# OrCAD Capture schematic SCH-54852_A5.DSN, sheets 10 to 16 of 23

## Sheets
10 C-12 USB PD: size C
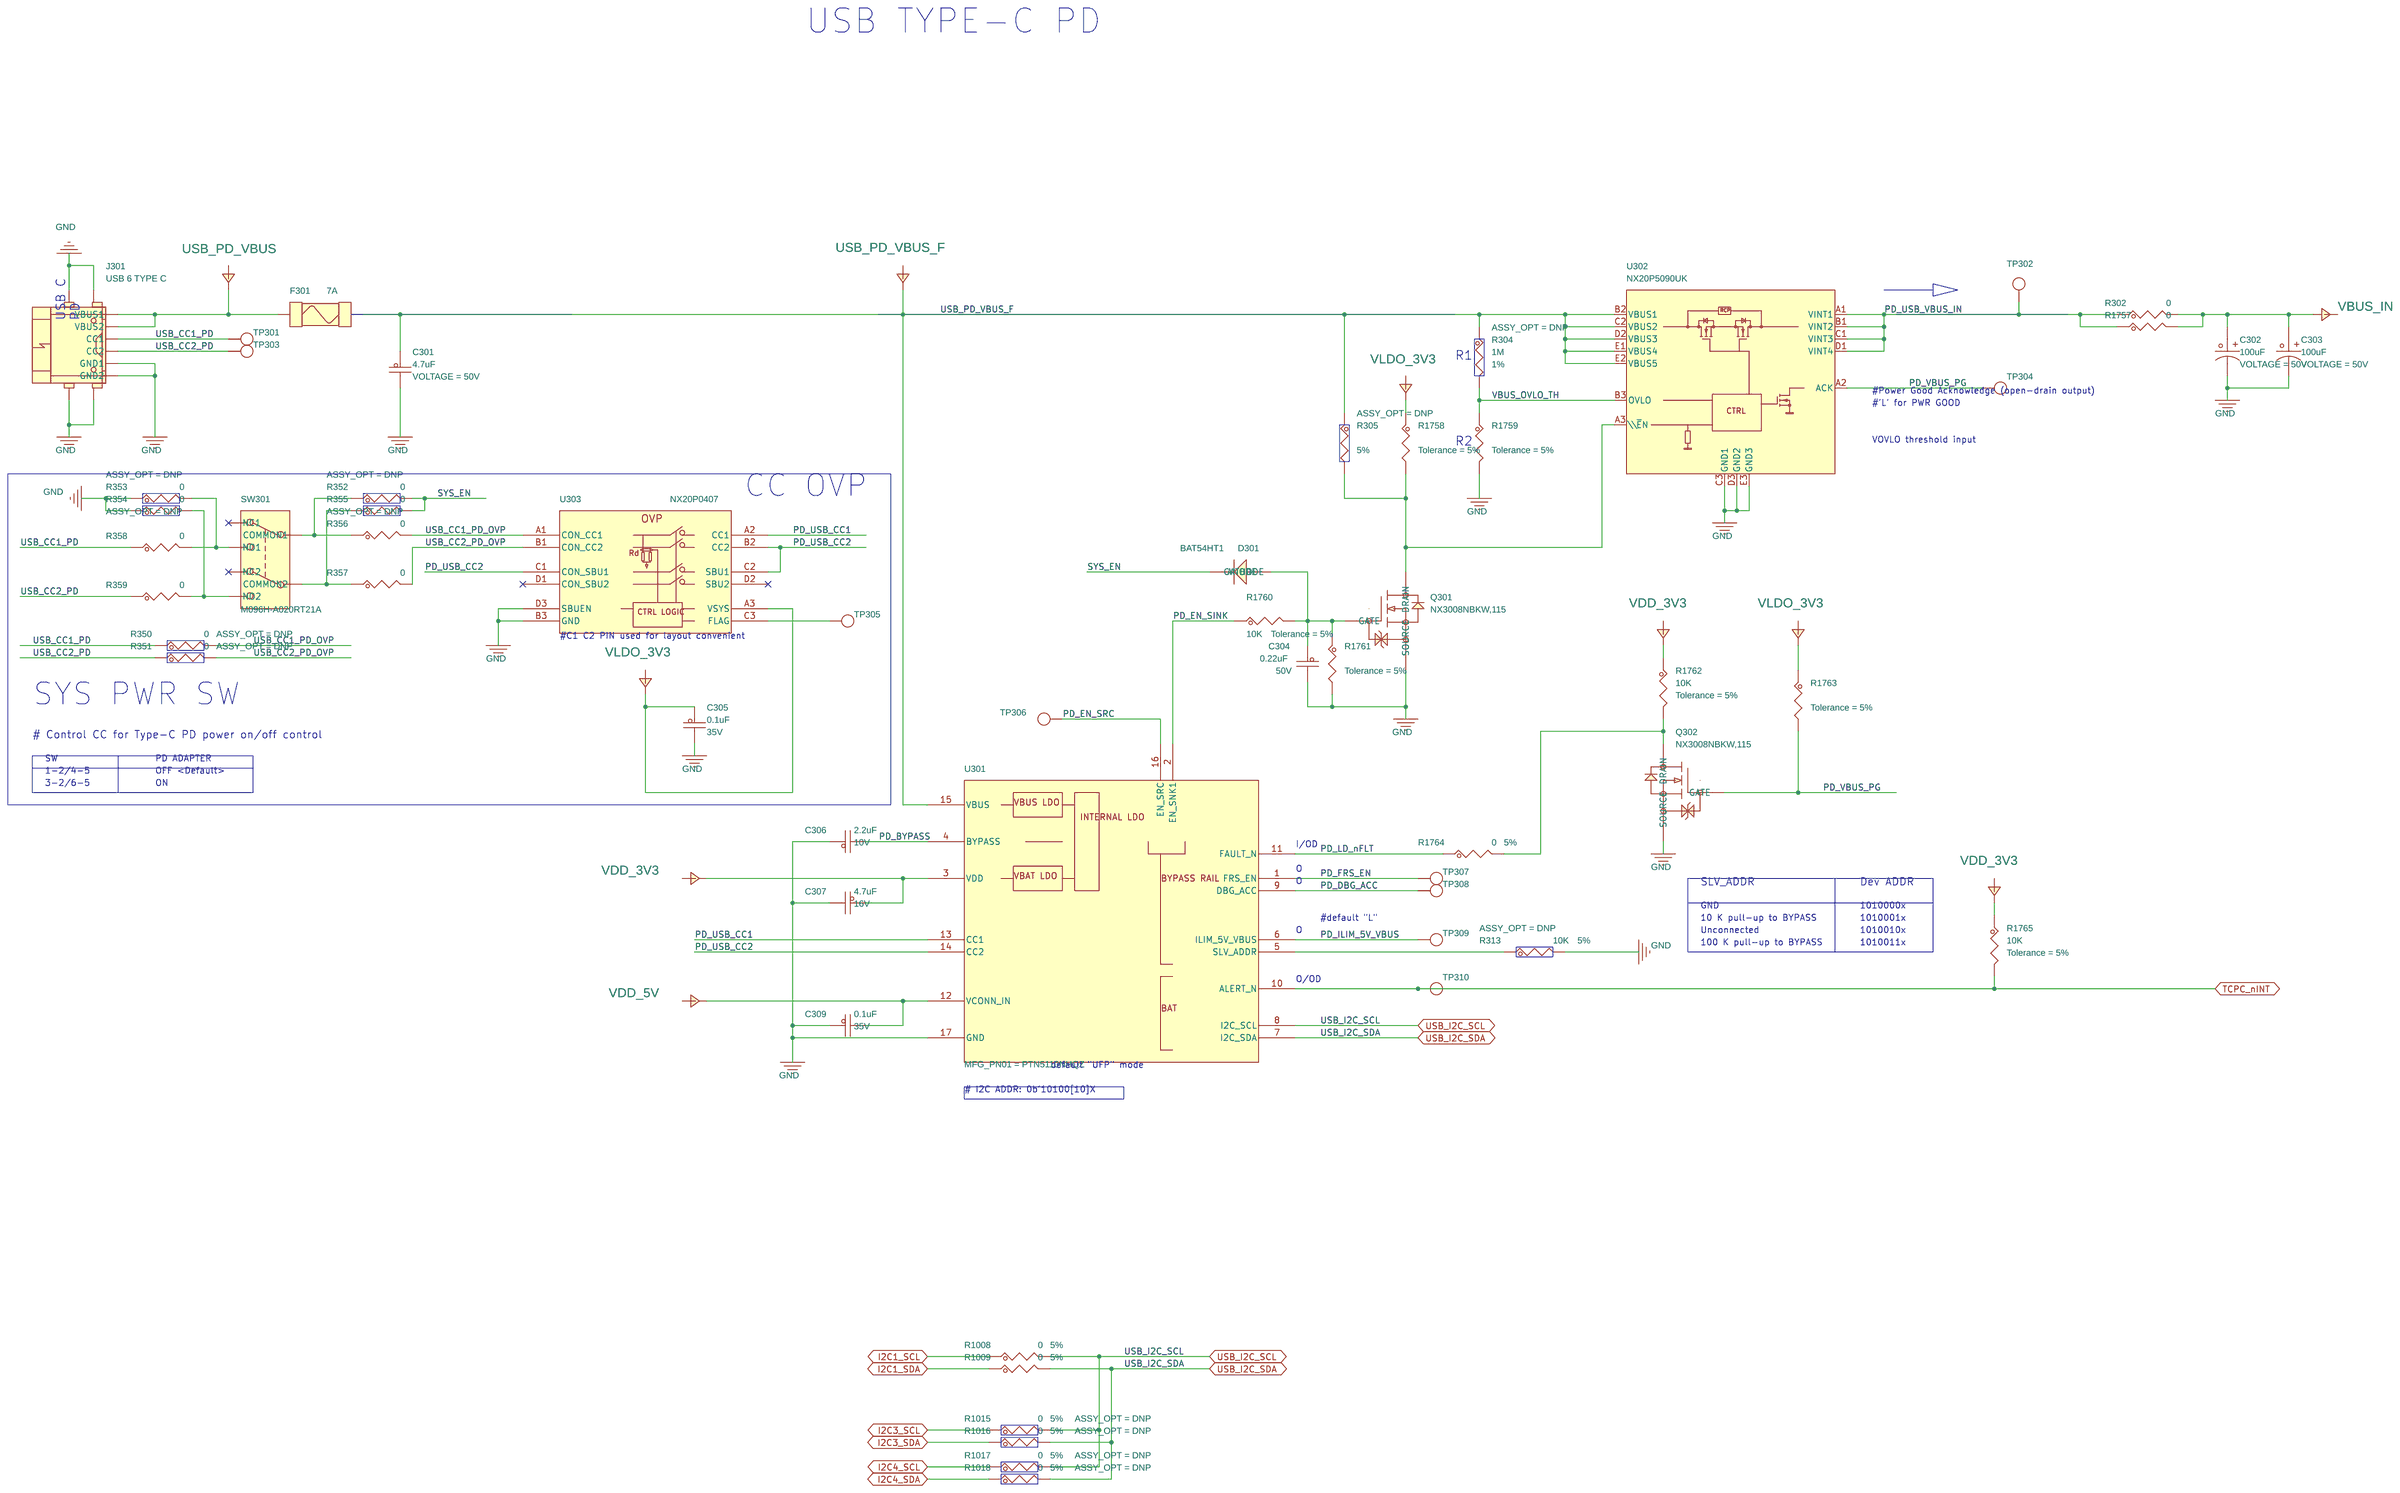
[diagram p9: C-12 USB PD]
11 C-11 SYS PWR: size C
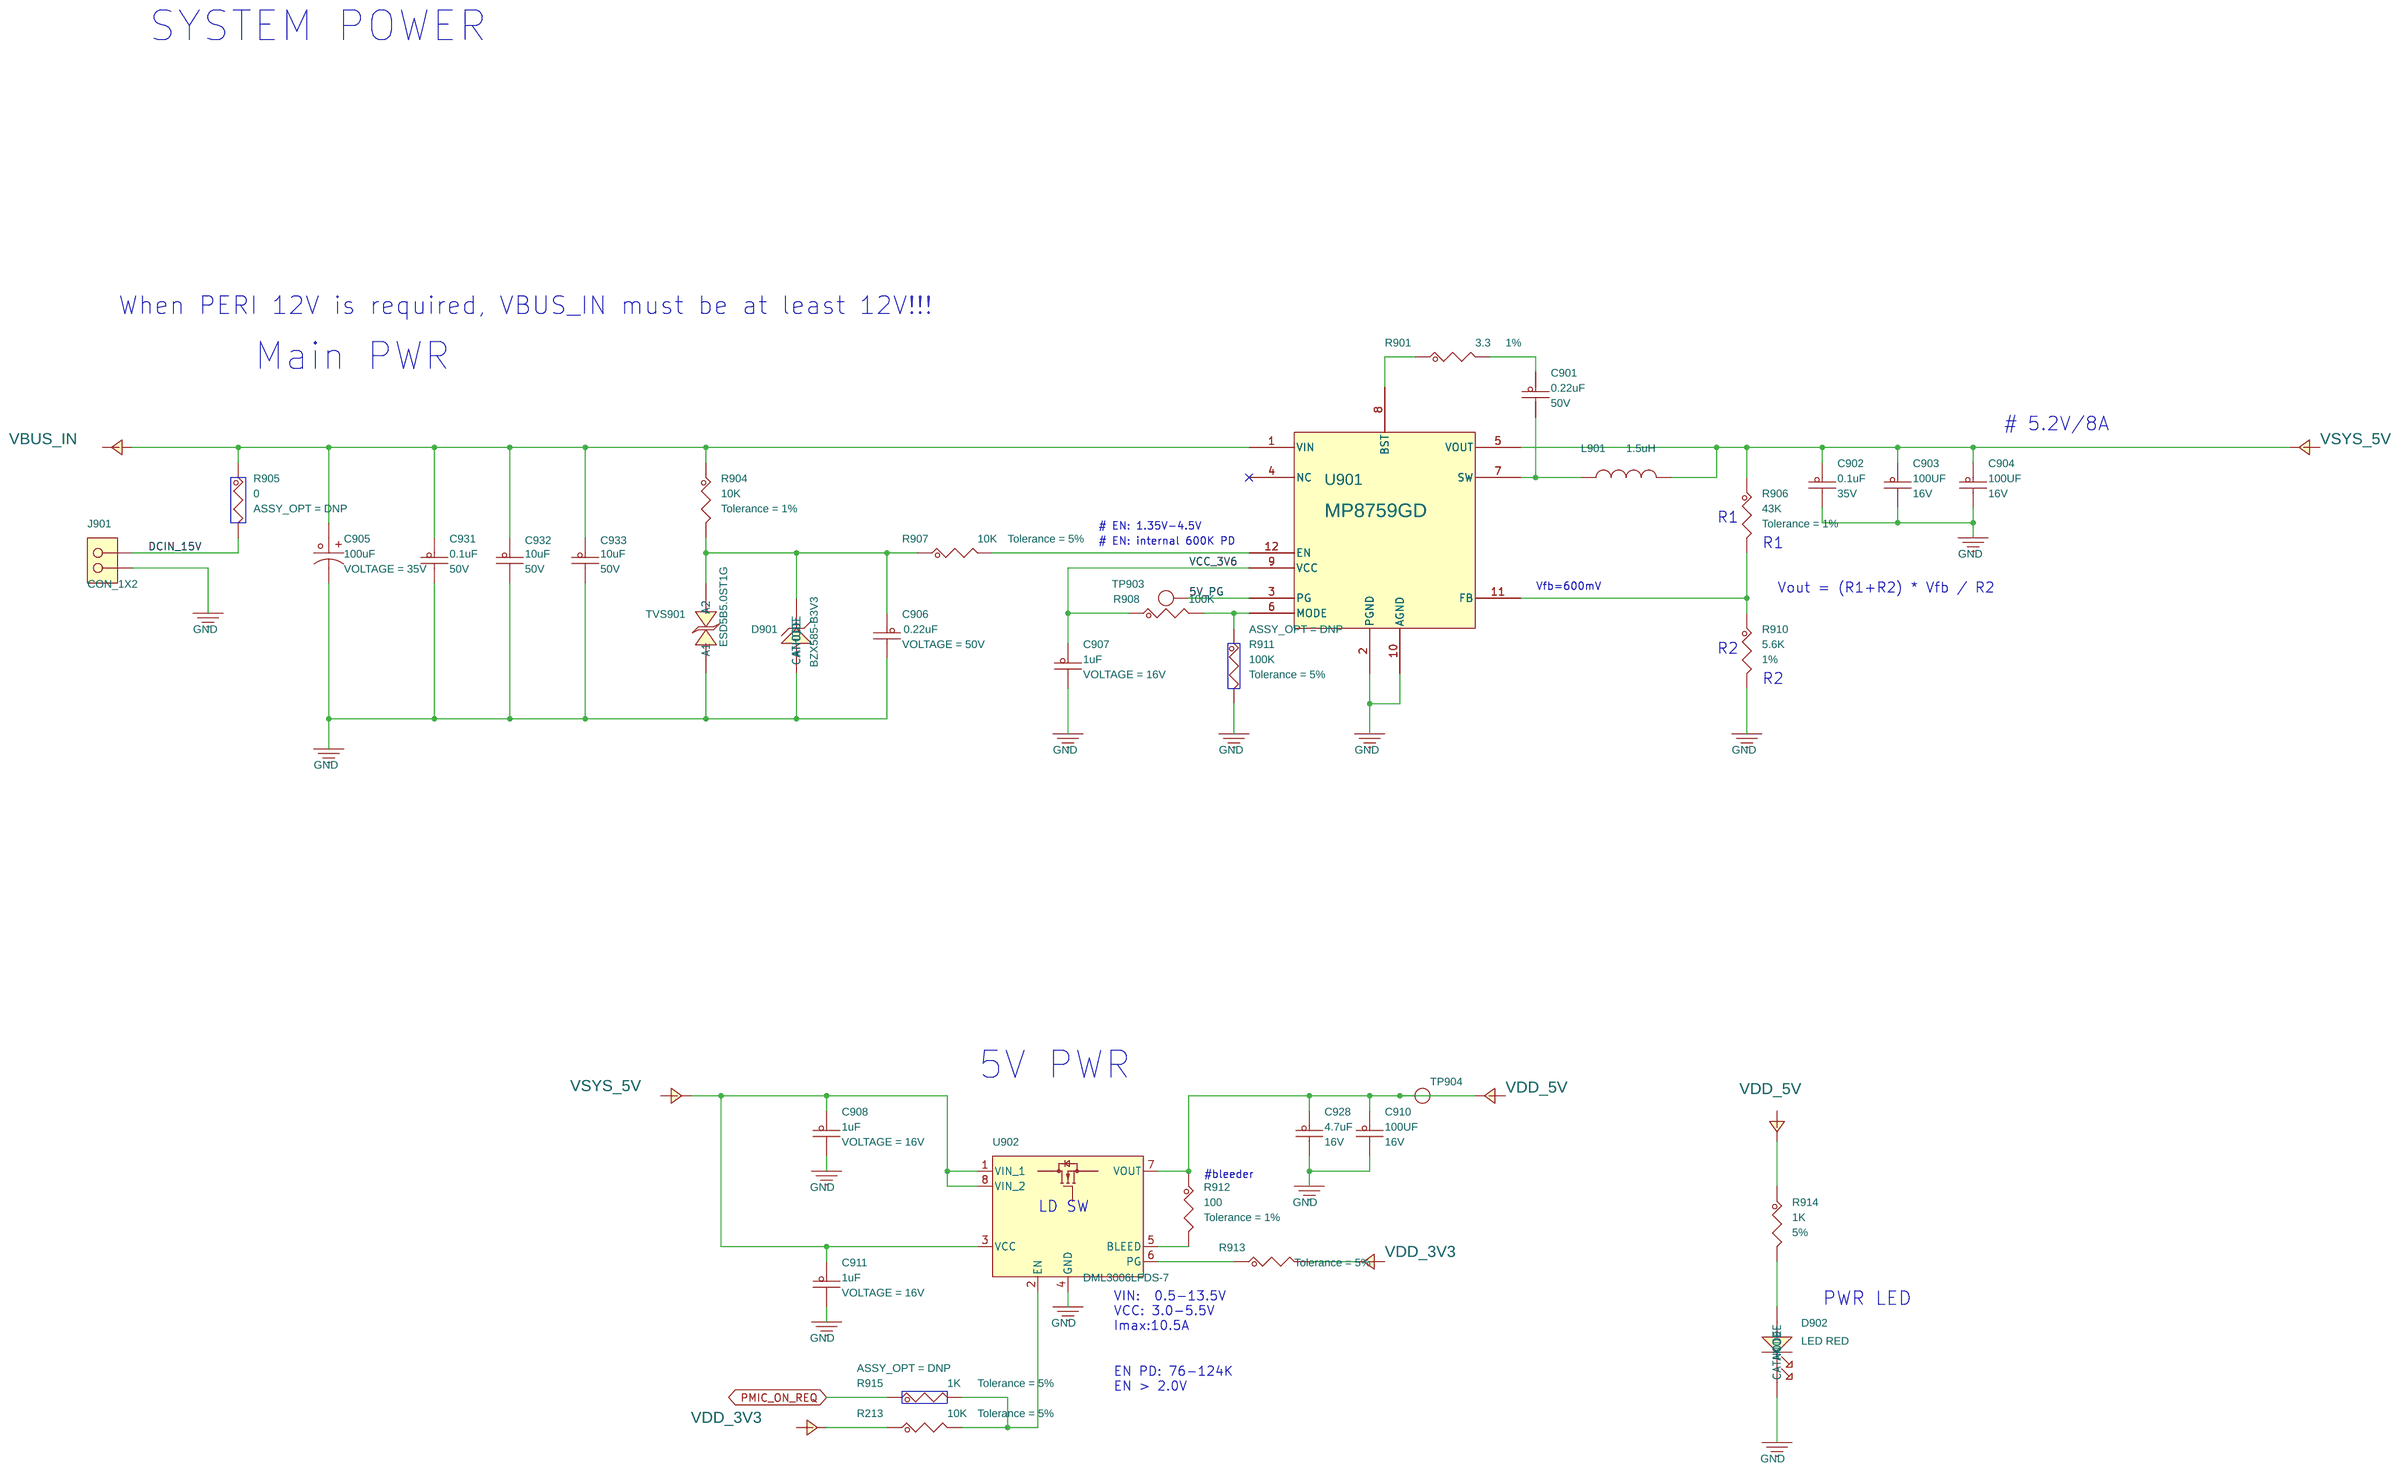
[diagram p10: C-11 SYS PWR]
12 C-10 IO MUX: size C
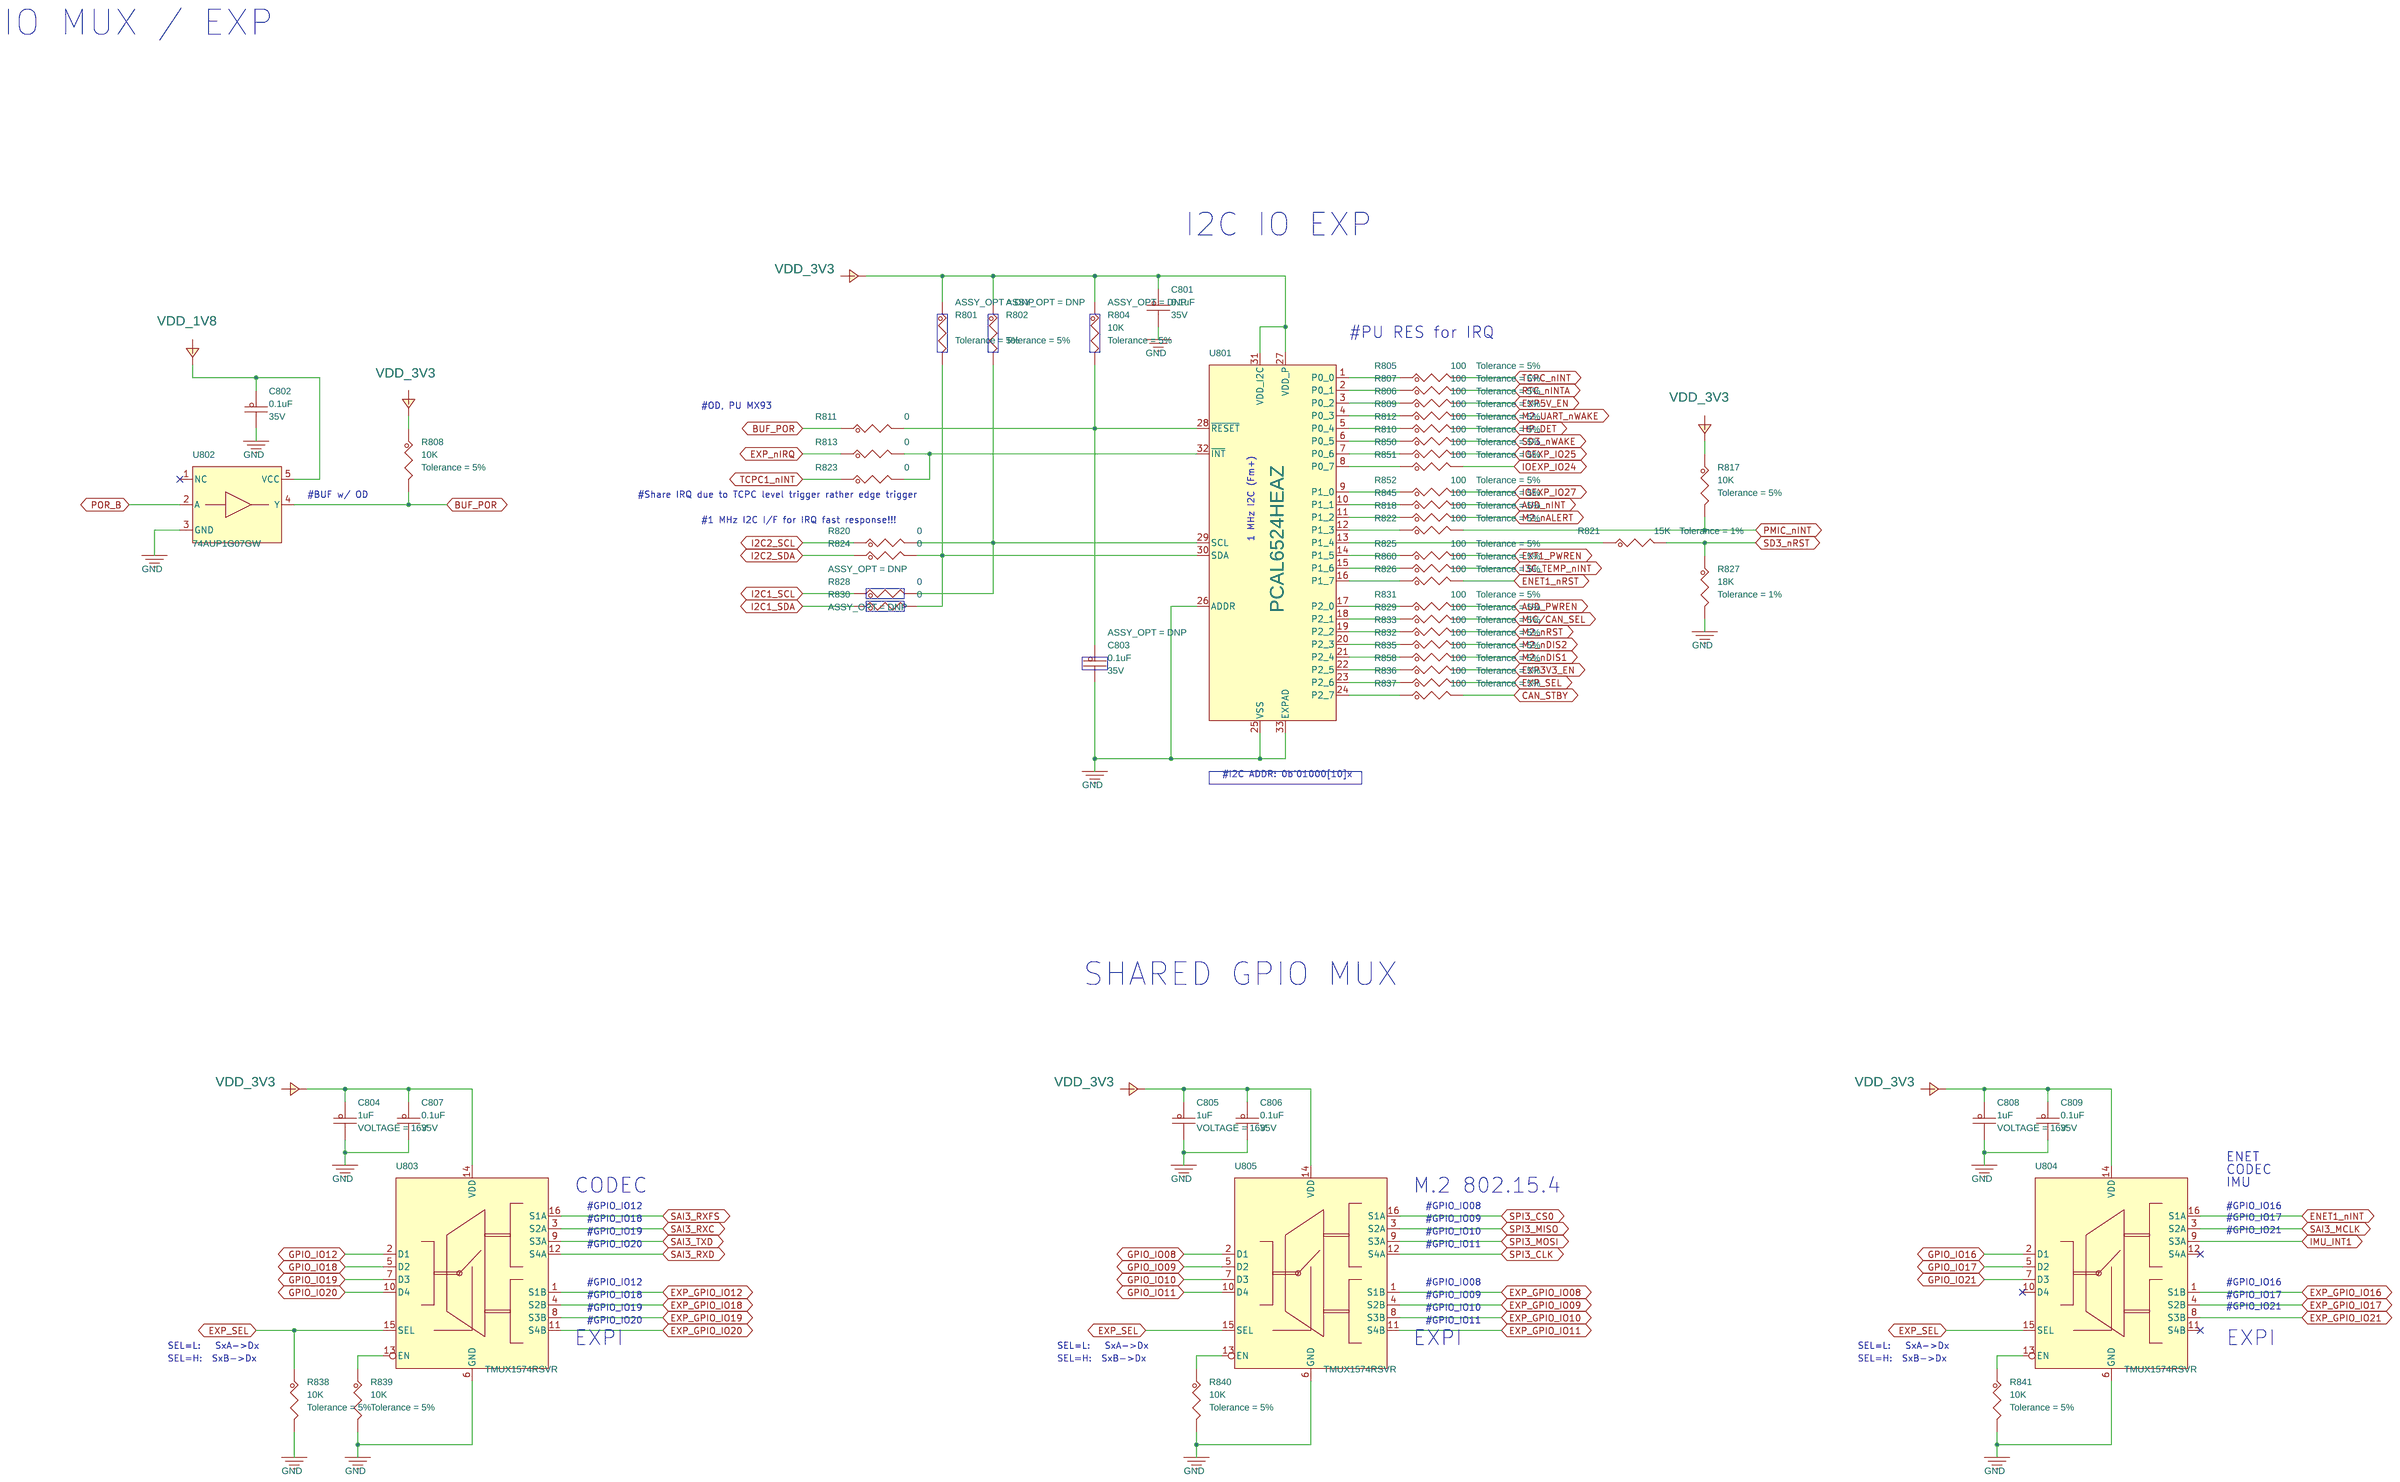
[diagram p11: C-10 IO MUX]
13 A-01 COVER
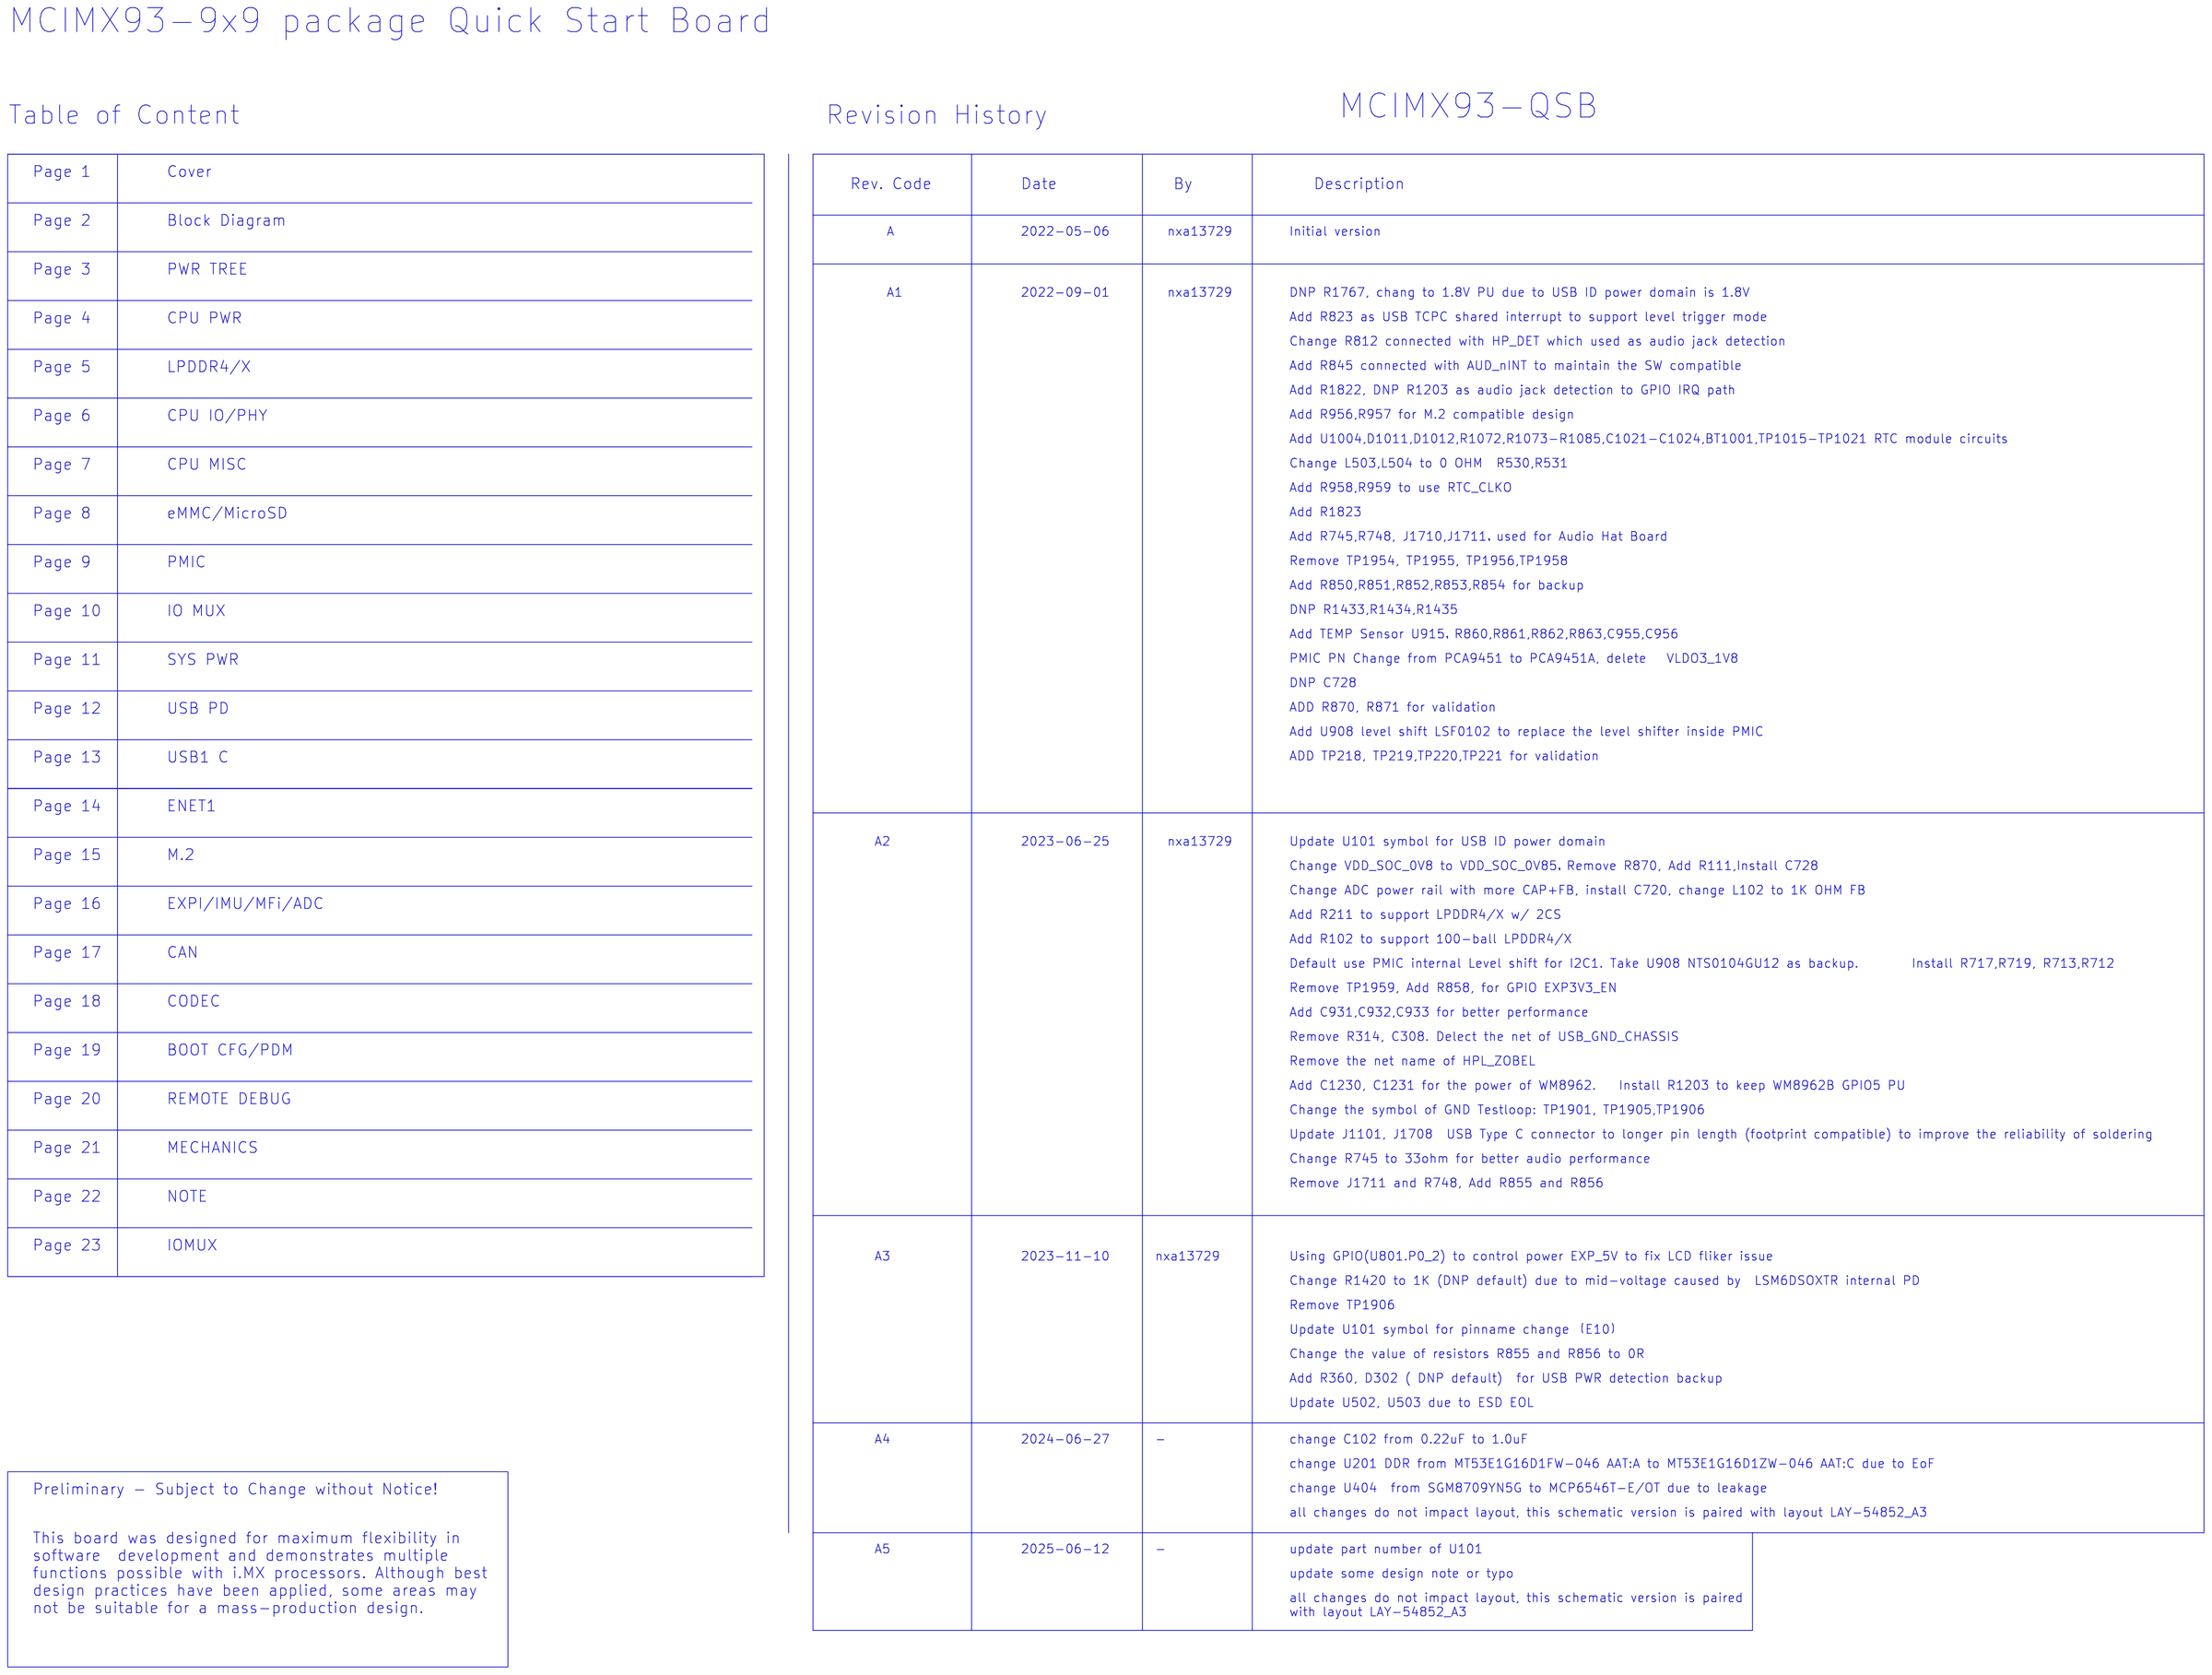
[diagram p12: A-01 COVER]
14 A-02 BLOCK DIAGRAM
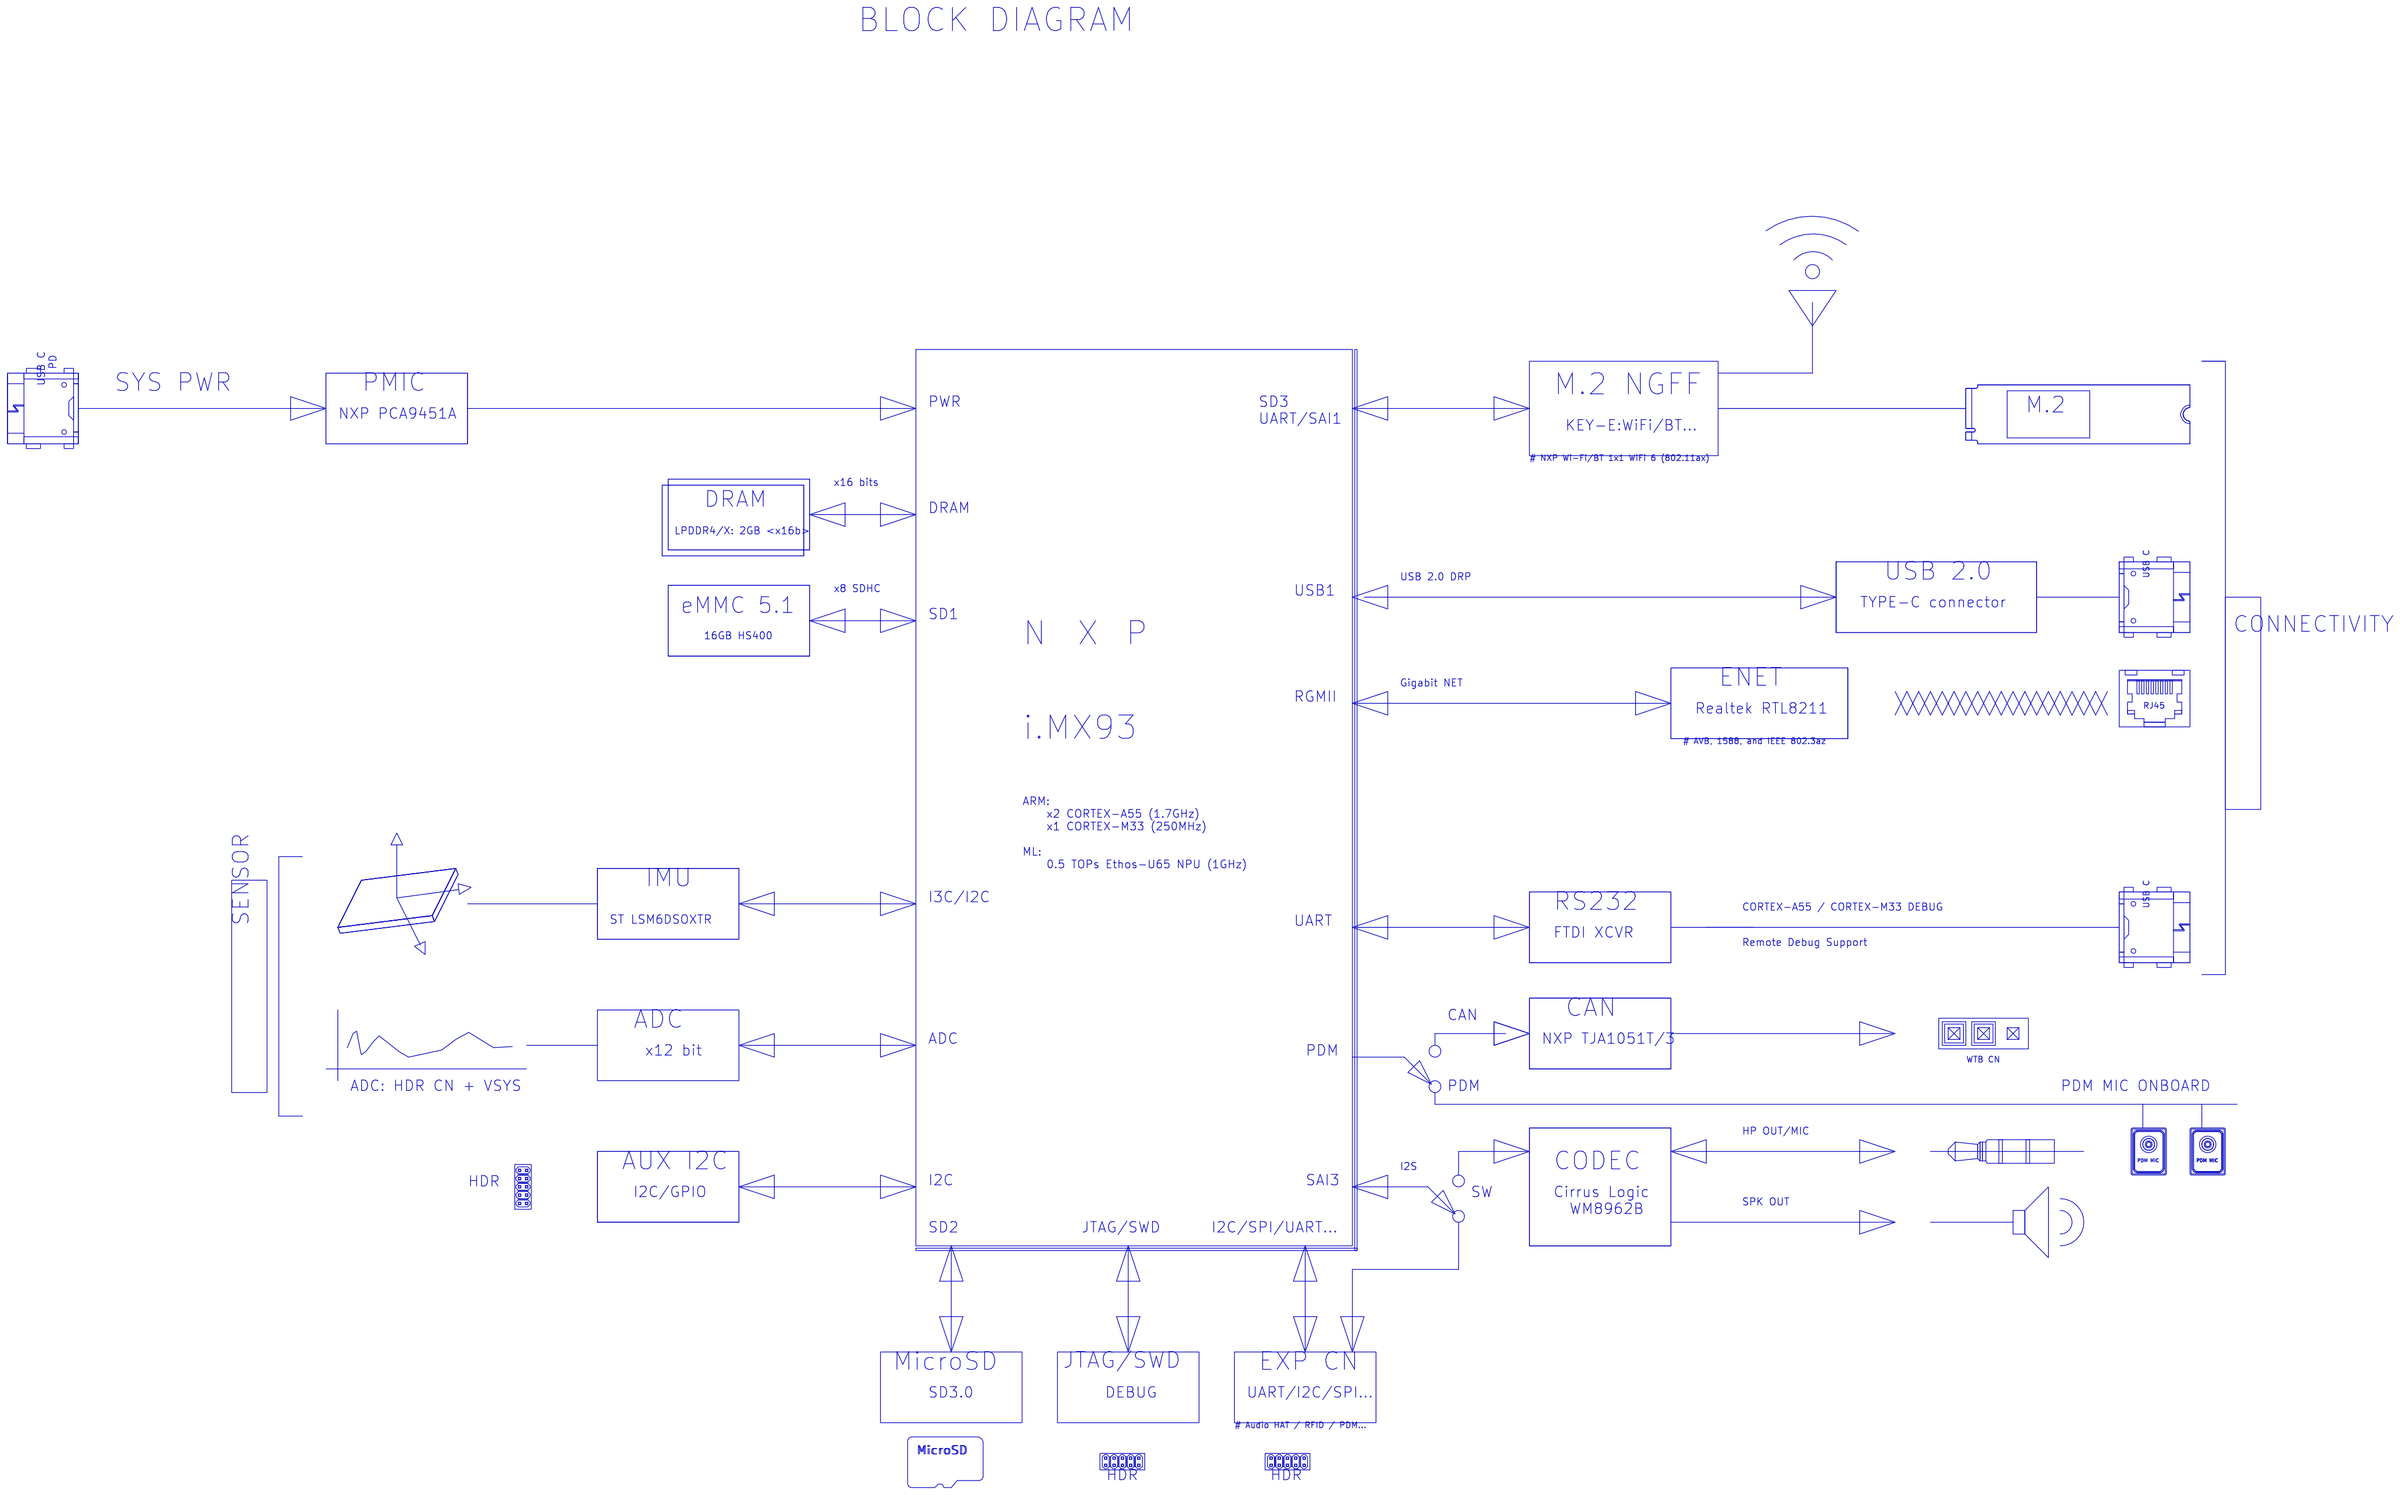
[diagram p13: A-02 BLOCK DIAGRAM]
15 A-03 PWR TREE
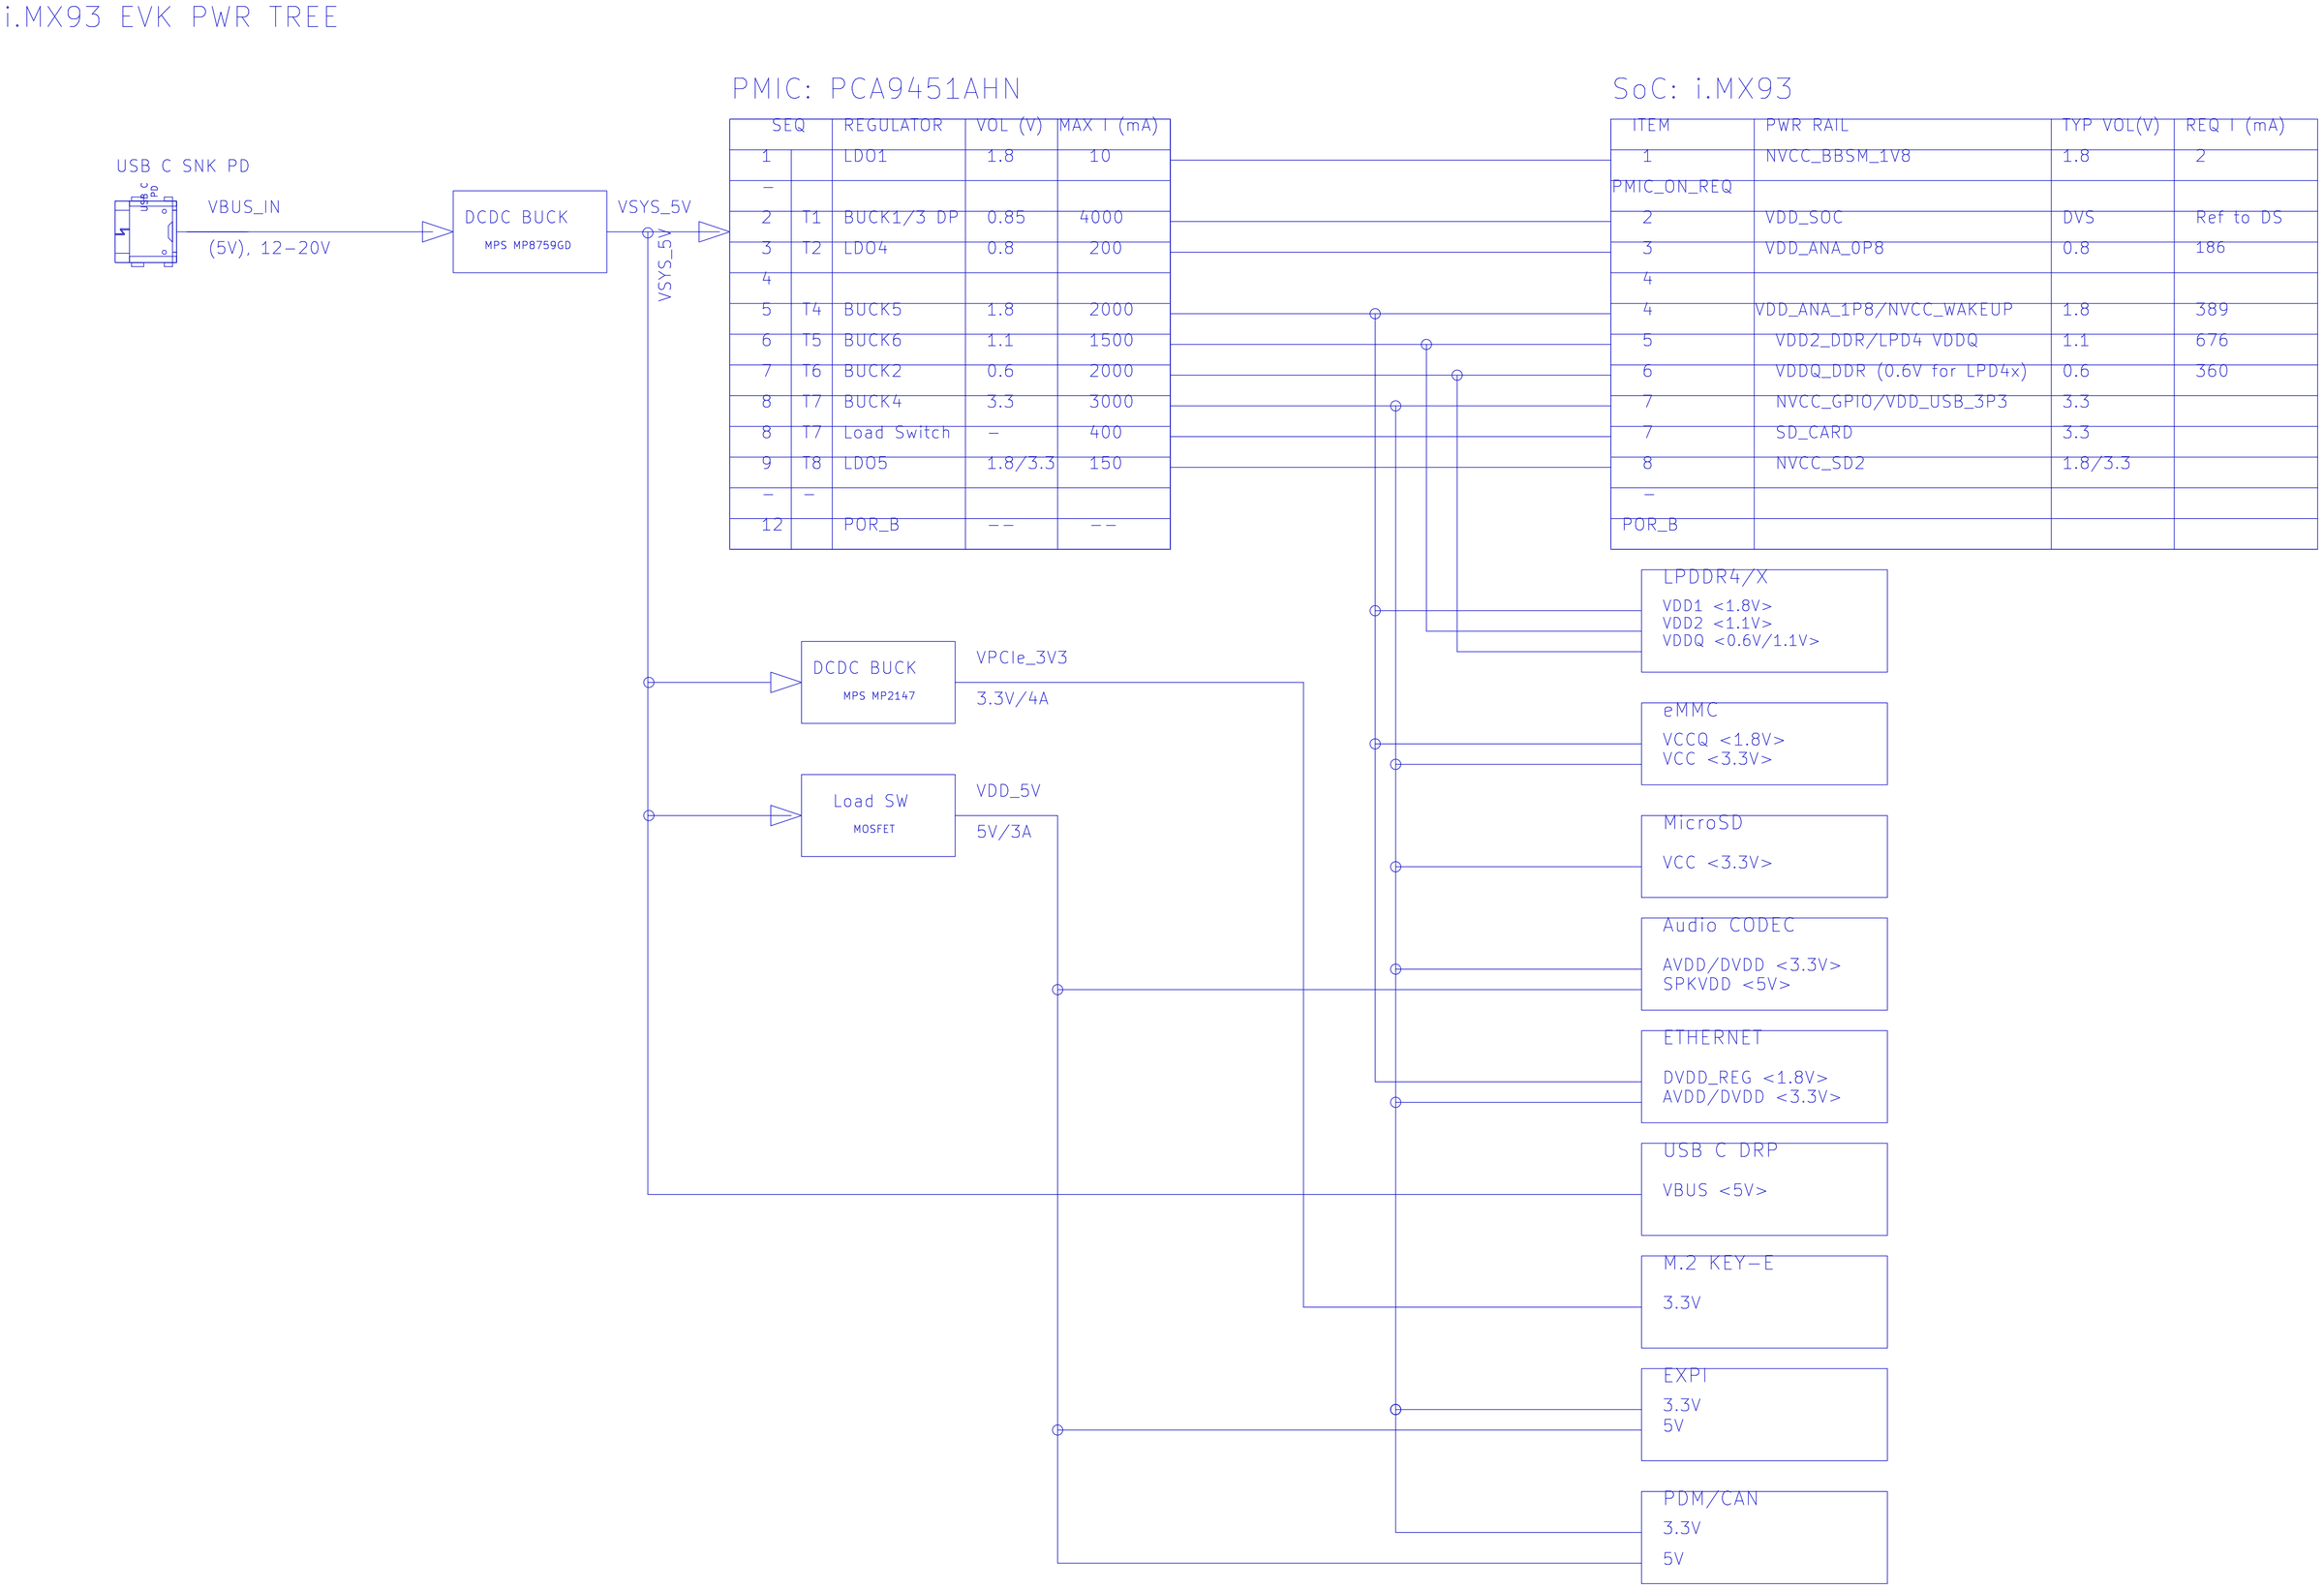
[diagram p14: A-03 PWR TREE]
16 C-04 CPU PWR: size C
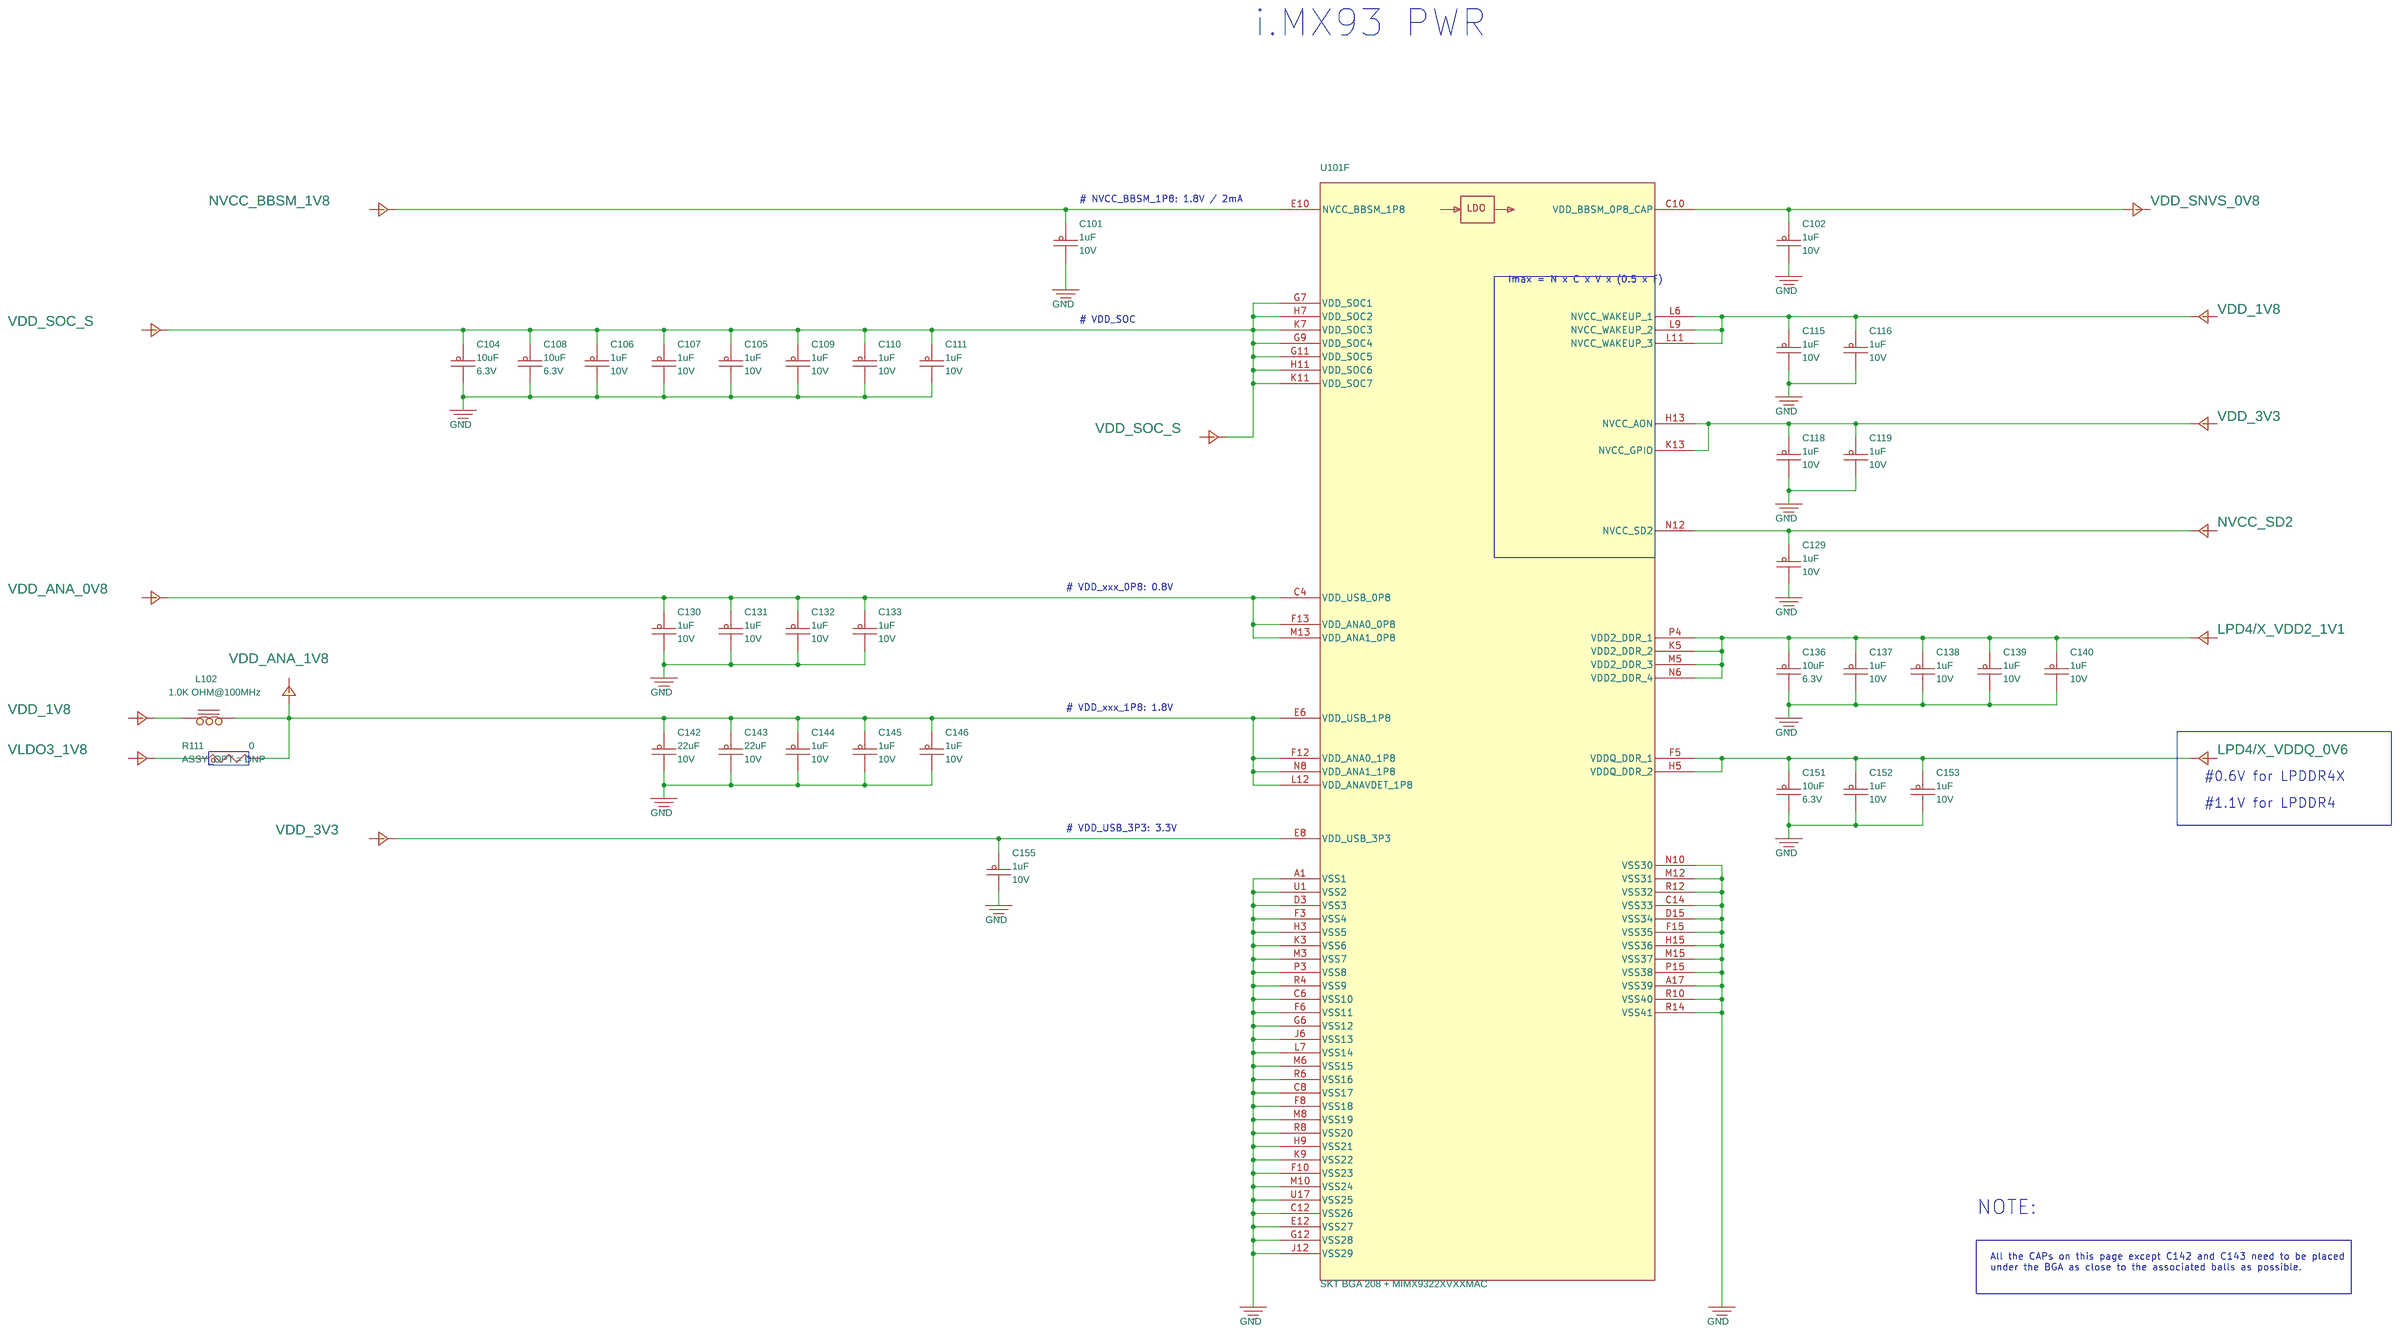
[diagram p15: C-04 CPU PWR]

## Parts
sheet C-04 CPU PWR
C101  1uF  [0201_CC]
C102  1uF  [0201_CC]
C104  10uF  [0402_CC]
C105  1uF  [0201_CC]
C106  1uF  [0201_CC]
C107  1uF  [0201_CC]
C108  10uF  [0402_CC]
C109  1uF  [0201_CC]
C110  1uF  [0201_CC]
C111  1uF  [0201_CC]
C115  1uF  [0201_CC]
C116  1uF  [0201_CC]
C118  1uF  [0201_CC]
C119  1uF  [0201_CC]
C129  1uF  [0201_CC]
C130  1uF  [0201_CC]
C131  1uF  [0201_CC]
C132  1uF  [0201_CC]
C133  1uF  [0201_CC]
C136  10uF  [0402_CC]
C137  1uF  [0201_CC]
C138  1uF  [0201_CC]
C139  1uF  [0201_CC]
C140  1uF  [0201_CC]
C142  22uF  [CC0603]
C143  22uF  [CC0603]
C144  1uF  [0201_CC]
C145  1uF  [0201_CC]
C146  1uF  [0201_CC]
C151  10uF  [0402_CC]
C152  1uF  [0201_CC]
C153  1uF  [0201_CC]
C155  1uF  [0201_CC]
L102  1.0K OHM@100MHz  [ind_0603]
R111  0  [0603_CC]
sheet C-06 CPU IO/PHY
U101  SKT BGA 208 + MIMX9322XVXXMAC  [skt_bga208_0p5_17p725sq_elast]  (sections A,B,C,D,E,F)
sheet C-10 IO MUX
C801  0.1uF  [CC0402_25]
C802  0.1uF  [CC0402_25]
C803  0.1uF  [CC0402_25]
C804  1uF  [CC0402_25]
C805  1uF  [CC0402_25]
C806  0.1uF  [CC0402_25]
C807  0.1uF  [CC0402_25]
C808  1uF  [CC0402_25]
C809  0.1uF  [CC0402_25]
R801  2.2K  [0402_CC]
R802  2.2K  [0402_CC]
R804  10K  [0402_CC]
R805  100  [RC0402_25]
R806  100  [RC0402_25]
R807  100  [RC0402_25]
R808  10K  [0402_CC]
R809  100  [RC0402_25]
R810  100  [RC0402_25]
R811  0  [0402_CC]
R812  100  [RC0402_25]
R813  0  [0402_CC]
R817  10K  [0402_CC]
R818  100  [RC0402_25]
R820  0  [0402_CC]
R821  15K  [RC0402_25]
R822  100  [RC0402_25]
R823  0  [0402_CC]
R824  0  [0402_CC]
R825  100  [RC0402_25]
R826  100  [RC0402_25]
R827  18K  [RC0402_25]
R828  0  [0402_CC]
R829  100  [RC0402_25]
R830  0  [0402_CC]
R831  100  [RC0402_25]
R832  100  [RC0402_25]
R833  100  [RC0402_25]
R835  100  [RC0402_25]
R836  100  [RC0402_25]
R837  100  [RC0402_25]
R838  10K  [0402_CC]
R839  10K  [0402_CC]
R840  10K  [0402_CC]
R841  10K  [0402_CC]
R845  100  [RC0402_25]
R850  100  [RC0402_25]
R851  100  [RC0402_25]
R852  100  [RC0402_25]
R858  100  [RC0402_25]
R860  100  [RC0402_25]
U801  PCAL6524HEAZ  [uqfn32_0p5_5x5_ep3x3]
U802  74AUP1G07GW  [sc70-5]
U803  TMUX1574RSVR  [pqfn16_0p4_2p65x1p85]
U804  TMUX1574RSVR  [pqfn16_0p4_2p65x1p85]
U805  TMUX1574RSVR  [pqfn16_0p4_2p65x1p85]
sheet C-11 SYS PWR
C901  0.22uF  [0402_CC]
C902  0.1uF  [CC0402_25]
C903  100UF  [1210_CC]
C904  100UF  [1210_CC]
C905  100uF  [case_d_al]
C906  0.22uF  [0402_CC]
C907  1uF  [CC0402_25]
C908  1uF  [CC0402_25]
C910  100UF  [1210_CC]
C911  1uF  [CC0402_25]
C928  4.7uF  [CC0603_OV]
C931  0.1uF  [0402_CC]
C932  10uF  [1210_CC]
C933  10uF  [1210_CC]
D901  BZX585-B3V3  [sod523]
D902  LED RED  [LED_0603]
J901  CON_1X2  [con2_2p5_7p96x5p96_th]
L901  1.5uH  [IND_IHLP]
R213  10K  [0402_CC]
R901  3.3  [0603_CC]
R904  10K  [0603_CC]
R905  0  [1206_CC]
R906  43K  [0402_CC]
R907  10K  [0402_CC]
R908  100K  [0402_CC]
R910  5.6K  [0402_CC]
R911  100K  [0402_CC]
R912  100  [RC0805_OV]
R913  100K  [0402_CC]
R914  1K  [0402_CC]
R915  1K  [0402_CC]
TP903  TPAD_050  [TPAD_050]
TP904  TPAD_050  [TPAD_050]
TVS901  ESD5B5.0ST1G  [diode2_sod523]
U901  MP8759GD  [qfn12_0p5_3p1x2p1]
U902  DML3006LFDS-7  [dfn2020_0p5_sq2]
sheet C-12 USB PD
C301  4.7uF  [CC1210]
C302  100uF  [cce8p3x8p3]
C303  100uF  [cce8p3x8p3]
C304  0.22uF  [0402_CC]
C305  0.1uF  [CC0402_25]
C306  2.2uF  [0402_CC]
C307  4.7uF  [CC0603_OV]
C309  0.1uF  [CC0402_25]
D301  BAT54HT1  [SOD323]
F301  7A  [fuse_3p4x1p8]
J301  USB 6 TYPE C  [usb6p_typec_ra_sm]
Q301  NX3008NBKW,115  [sc70_3]
Q302  NX3008NBKW,115  [sc70_3]
R302  0  [0805_CC]
R304  1M  [0402_CC]
R305  100K  [0402_CC]
R313  10K  [0402_CC]
R350  0  [0402_CC]
R351  0  [0402_CC]
R352  0  [0402_CC]
R353  0  [0402_CC]
R354  0  [0402_CC]
R355  0  [0402_CC]
R356  0  [0402_CC]
R357  0  [0402_CC]
R358  0  [0402_CC]
R359  0  [0402_CC]
R1008  0  [0402_CC]
R1009  0  [0402_CC]
R1015  0  [0402_CC]
R1016  0  [0402_CC]
R1017  0  [0402_CC]
R1018  0  [0402_CC]
R1757  0  [0805_CC]
R1758  100K  [0402_CC]
R1759  100K  [0402_CC]
R1760  10K  [0402_CC]
R1761  100K  [0402_CC]
R1762  10K  [0402_CC]
R1763  100K  [0402_CC]
R1764  0  [0402_CC]
R1765  10K  [0402_CC]
SW301  M096H-A020RT21A  [sw6_dpdt_m096h_th]
TP301  TPAD_020  [tpad_020]
TP302  TPAD_050  [TPAD_050]
TP303  TPAD_020  [tpad_020]
TP304  TPAD_050  [TPAD_050]
TP305  TPAD_020  [tpad_020]
TP306  TPAD_020  [tpad_020]
TP307  TPAD_020  [tpad_020]
TP308  TPAD_020  [tpad_020]
TP309  TPAD_020  [tpad_020]
TP310  TPAD_020  [tpad_020]
U301  PTN5110  [hx2qfn16_0p4_2p7x2p7]
U302  NX20P5090UK  [wlcsp15_0p5_1p57x2p59]
U303  NX20P0407  [wlcsp12_0p4_1p3x1p7mm_smdp]

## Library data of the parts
C101 C102 C105-C107 C109-C111 C115 C116 C118 C119 C129-C133 C137-C140 C144-C146 C152 C153 C155 = CAP_NP: CAP CER 1.0uF 10V 10% X5R 0201; AGILE_PN: 150-81088; CAD_APPROVED: Yes; FPLIST: CC0201,CC0201_HD,0201_CC,cc_0201_cir; HEIGHT: 0.35MM; MFG_NAME01: SAMSUNG ELECTRO MECHANICS; MFG_PN01: CL03A105KP3NSNC; Package Size: 0201 (0603 Metric); Package Type: SMD/SMT; ROHS: Yes; Temp Range: -55°C to 85°C; Tolerance: 10%; VOLTAGE: 10V
C104 C108 C136 C151 = CAP_NP: CAP CER 10UF 6.3V 20% X5R 0402; 3D_Mechanical_Footprint_File: cc0402_tol0p2; AGILE_PN: 150-79163; CAD_APPROVED: Yes; FPLIST: CC0402_25,CC0402_HD,0402_CC; HEIGHT: 0.7 MM; MFG_NAME01: SAMSUNG ELECTRO MECHANICS; MFG_PN01: CL05A106MQ5NUNC; ROHS: Yes; Tolerance: 20%; VOLTAGE: 6.3V
C142 C143 = CAP_NP: CAP CER 22uF 10V 20% X5R 0603; AGILE_PN: 150-79530; CAD_APPROVED: Yes; FPLIST: CC0603_OV,CC0603,0603_cc_tol; HEIGHT: 1MM; MFG_NAME01: TDK; MFG_PN01: C1608X5R1A226M080AC; Package Size: 0603; ROHS: Yes; SIGNAL_MODEL: DEFAULT_CAPACITOR_2.2e+07pF_2_1; Tolerance: 20%; VOLTAGE: 10V; WVDC: 6.3V
L102 = INDUCTOR_FERRITE_0: IND FER BEAD 1.0K OHM@100MHz 1.2A 25% 0603; 3D_Mechanical_Footprint_File: http://fcl.am.freescale.net/ALLEGRO/step/ind_0603.STEP; AGILE_PN: 180-81296; CAD_APPROVED: Yes; FPLIST: ind_0603,0603_cc; HEIGHT: 0.95MM; MFG_NAME01: MURATA; MFG_PN01: BLM18SP102SN1D; Package Size: 0603 (1608 Metric); ROHS: Yes; Temp Range: -55°C to +125°C
R111 = RES: RES MF ZERO OHM 1/10W -- 0603; AGILE_PN: 470-80866; ASSY_OPT: DNP; CAD_APPROVED: Yes; FPLIST: RC0603_OV,RC0603,R603-X2,0603_CC,IND_0603HP_NSP,CC0603_OV_NSP; HEIGHT: 0.6MM; MFG_NAME01: WALSIN TECHNOLOGY CORP.; MFG_PN01: WR06X000PTL; ROHS: Yes; Temp Range: –55 °C to +155 °C
U101 = MIMX9322XVXxMAB_BGA208: SUBASSEMBLY SKT 208 BGA ELASTOMER SMT 0.5MM 414H AU + IC CPU CORTEX 2xA55 1.7GHz 3.2GT/s DDR -- FCPBGA208; AGILE_PN: TMP-CIP-20687; CAD_APPROVED: Yes; HEIGHT: 10.503mm; MFG_NAME01: SUBASSEMBLY; MFG_PN01: 211-81858,330-10033; PRE_APN: 750-10191; Package Type: SMD/SMT; ROHS: Yes
C305 C309 C801 C802 C806 C807 C809 C902 = CAP_NP: CAP CER 0.1UF 35V 10% X5R 0402; AGILE_PN: 150-78506; CAD_APPROVED: Yes; FPLIST: CC0402_25,CC0402_HD,0402_CC,capc0402_l; HEIGHT: 0.55MM; MFG_NAME01: TAIYO YUDEN; MFG_PN01: GMK105BJ104KV-F; ROHS: Yes; Tolerance: 10%; VOLTAGE: 35V
C803 = CAP_NP: CAP CER 0.1UF 35V 10% X5R 0402; AGILE_PN: 150-78506; ASSY_OPT: DNP; CAD_APPROVED: Yes; FPLIST: CC0402_25,CC0402_HD,0402_CC,capc0402_l; HEIGHT: 0.55MM; MFG_NAME01: TAIYO YUDEN; MFG_PN01: GMK105BJ104KV-F; ROHS: Yes; Tolerance: 10%; VOLTAGE: 35V
C804 C805 C808 C907 = CAP_NP: CAP CER 1uF 16V 10% X5R 0402; AGILE_PN: 150-78973; CAD_APPROVED: Yes; FPLIST: CC0402_25,CC0402_HD,0402_CC,capc0402_l; HEIGHT: 0.55 MM; MFG_NAME01: YAGEO; MFG_PN01: CC0402KRX5R7BB105; ROHS: Yes; SIGNAL_MODEL: DEFAULT_CAPACITOR_1e+06pF_2_1; TOL: 10%; Tolerance: 10%; VOLTAGE: 16V; voltage rating: 10V
R801 R802 = RES: RES MF 2.2K 1/16W 5% 0402; AGILE_PN: 470-76602; ASSY_OPT: DNP; CAD_APPROVED: Yes; FPLIST: RC0402_25,RC0402_HD,0402_CC; HEIGHT: 0.4 MM; MFG_NAME01: YAGEO AMERICA; MFG_PN01: RC0402JR-072K2L; RATING: 1/16W; ROHS: Yes; Tolerance: 5%
R313 R804 = RES: RES MF 10K 1/16W 5% 0402; AGILE_PN: 470-75557; ASSY_OPT: DNP; CAD_APPROVED: Yes; FPLIST: RC0402_25,RC0402_HD,0402_CC; HEIGHT: 0.4 MM; MFG_NAME01: VISHAY INTERTECHNOLOGY; MFG_PN01: CRCW040210K0JNED; ROHS: Yes; Tolerance: 5%
R805-R807 R809 R810 R812 R818 R822 R825 R826 R829 R831-R833 R835-R837 R845 R850-R852 R858 R860 = RES: RES MF 100 OHM 1/16W 5% 0402; AGILE_PN: 470-82142; CAD_APPROVED: Yes; FPLIST: RC0402_25,RC0402_HD,RC0402_X2,0402_CC; HEIGHT: 0.45MM; MFG_NAME01: SMEC; MFG_PN01: RC73L2Z101JTF; ROHS: Yes; Temp Range: -55°C to +175°C; Tolerance: 5%
R213 R808 R817 R838-R841 R907 R1760 R1762 R1765 = RES: RES MF 10K 1/16W 5% 0402; AGILE_PN: 470-75557; CAD_APPROVED: Yes; FPLIST: RC0402_25,RC0402_HD,0402_CC; HEIGHT: 0.4 MM; MFG_NAME01: VISHAY INTERTECHNOLOGY; MFG_PN01: CRCW040210K0JNED; ROHS: Yes; Tolerance: 5%
R811 R813 R820 R823 R824 R1008 R1009 = RES: RES MF ZERO OHM 1/16W 5% 0402; AGILE_PN: 470-75394; CAD_APPROVED: Yes; FPLIST: RC0402_25,RC0402_HD,RC0402_X2,0402_CC; HEIGHT: 0.45 MM; MFG_NAME01: YAGEO AMERICA; MFG_PN01: RC0402JR-070RL; ROHS: Yes; Tolerance: 5%; VOLTAGE: 1/16W
R821 = RES: RES MF 15.0K 1/16W 1% 0402; AGILE_PN: 470-76066; CAD_APPROVED: Yes; FPLIST: RC0402_25,RC0402_HD,0402_CC; HEIGHT: 0.4 MM; MFG_NAME01: NIC COMPONENTS CORP; MFG_PN01: NRCL04F1502TRF; ROHS: Yes; Tolerance: 1%
R827 = RES: RES MF 18K 1/16W 1% 0402; AGILE_PN: 470-82139; CAD_APPROVED: Yes; FPLIST: RC0402_25,RC0402_HD,0402_CC; HEIGHT: 0.4MM; MFG_NAME01: NIC COMPONENTS CORP; MFG_PN01: NRCL04F1802TRF; ROHS: Yes; Temp Range: -55°C to +155°C; Tolerance: 1%; VOLTAGE: 50V
R828 R830 R1015-R1018 = RES: RES MF ZERO OHM 1/16W 5% 0402; AGILE_PN: 470-75394; ASSY_OPT: DNP; CAD_APPROVED: Yes; FPLIST: RC0402_25,RC0402_HD,RC0402_X2,0402_CC; HEIGHT: 0.45 MM; MFG_NAME01: YAGEO AMERICA; MFG_PN01: RC0402JR-070RL; ROHS: Yes; Tolerance: 5%; VOLTAGE: 1/16W
U801 = PCAL6524HE_QFN: IC I/O EXPANDER 24-BIT I2C 0.8-3.6V/1.65-5.5V UQFN32; 3D_Mechanical_Footprint_File: ftp://fcl.am.freescale.net/ALLEGRO/step/uqfn32_0p5_5x5_ep3x3.step; AGILE_PN: 315-81642; CAD_APPROVED: Yes; HEIGHT: 0.6MM; MFG_NAME01: NXP SEMICONDUCTORS; ROHS: Yes; Temp Range: -40C to +85C; VOLTAGE: 0.8-3.6V/1.65-5.5
U802 = 74AUP1G07GW: IC LOGIC GATE BUFFER 0.8-3.6V TSSOP5; AGILE_PN: 312-81232; CAD_APPROVED: Yes; HEIGHT: 1.1MM; MFG_NAME01: NEXPERIA; MFG_PN01: 74AUP1G07GW,125; ROHS: Yes; VOLTAGE: 0.8-3.6V
U803-U805 = TMUX1574RSVR_A: IC MUX SW SPDT 1.8V UQFN16; AGILE_PN: 312-82341; CAD_APPROVED: Yes; HEIGHT: 0.55MM; MFG_NAME01: TEXAS INSTRUMENTS; ROHS: Yes; Temp Range: -40C to +125C; VOLTAGE: 1.5-5.5V
C901 C906 = CAP_NP: CAP CER 0.22uF 50V 10% X5R 0402; AGILE_PN: 150-79999; CAD_APPROVED: Yes; FPLIST: CC0402_25,CC0402_HD,0402_CC,capc0402_l; HEIGHT: 0.55MM; MFG_NAME01: TAIYO YUDEN; MFG_PN01: UMK105BJ224KV-F; Package Size: 0402; ROHS: Yes; Temp Range: -55°C to +85°C; Temp_Range: -55°C to +85°C; Tolerance: 10%; VOLTAGE: 50V
C903 C904 C910 = CAP_NP: CAP CER 100uF 16V 20% X5R 1210; AGILE_PN: 150-79142; CAD_APPROVED: Yes; FPLIST: CC1210,1210_CC; HEIGHT: 2.8MM; MFG_NAME01: TAIYO YUDEN; MFG_PN01: EMK325ABJ107MM-T; Package Size: 1210; ROHS: Yes; Tolerance: 20%; VOLTAGE: 16V
C905 = CAP_POL: CAP ALEL 100uF 35V 20% AEC-Q200 SMT; AGILE_PN: 150-80610; CAD_APPROVED: Yes; HEIGHT: 6.1mm; MFG_NAME01: PANASONIC; MFG_PN01: EEEFT1V101AP; Package Type: SMT; ROHS: Yes; Temp Range: –55 °C to +105 °C; Tolerance: 20%; VOLTAGE: 35V
C908 C911 = CAP_NP: CAP CER 1uF 16V 10% X5R 0402; AGILE_PN: 150-78973; CAD_APPROVED: Yes; FPLIST: CC0402_25,CC0402_HD,0402_CC,capc0402_l; HEIGHT: 0.55 MM; MFG_NAME01: YAGEO; MFG_PN01: CC0402KRX5R7BB105; ROHS: Yes; Tolerance: 10%; VOLTAGE: 16V
C928 = CAP_NP: CAP CER 4.7uF 16V 10% X5R 0603; AGILE_PN: 150-80061; CAD_APPROVED: Yes; EN: 102-1-01650; FPLIST: CC0603_OV,CC0603,cc0603_0805_nsp,0603_CC_NSP; HEIGHT: 0.95MM; MFG_NAME01: MURATA; MFG_PN01: GRM188R61C475KE11D; ROHS: Yes; TOL: 10%; Temp Range: -55°C to + 85°C; VOLTAGE: 16V
C931 = CAP_NP: CAP CER 0.1uF 50V 10% X7R 0402; AGILE_PN: 150-79069; CAD_APPROVED: Yes; FPLIST: CC0402_25,CC0402_HD,0402_CC,capc0402_l; HEIGHT: 0.6 MM; MFG_NAME01: MURATA; MFG_PN01: GRM155R71H104KE14D; ROHS: Yes; Tolerance: 10%; VOLTAGE: 50V
C932 C933 = CAP_NP: CAP CER 10uF 50V 10% X7R 1210; AGILE_PN: 150-79919; CAD_APPROVED: Yes; FPLIST: CC1210,1210_CC; HEIGHT: 2.7MM; MFG_NAME01: SAMSUNG; MFG_PN01: CL32B106KBJNNNE; Package Size: 1210; Package Type: Embossed Type, 7" reel; ROHS: Yes; Temp Range: -55°C to +125°C; Tolerance: 10%; VOLTAGE: 50V
D901 = ZDIODE: DIODE ZNR 0.3W 3.3V 200mA AEC-Q101 SOD-523; AGILE_PN: 480-79870; CAD_APPROVED: Yes; HEIGHT: 0.65MM; MFG_NAME01: NEXPERIA; ROHS: Yes; Temp Range: -65°C to +150°C; Temp_Range: -65°C to +150°C
D902 = LED: LED RED SGL 25MA 0603; AGILE_PN: 370-76658; CAD_APPROVED: Yes; HEIGHT: 0.8 MM; MFG_NAME01: DIALIGHT; MFG_PN01: 598-8010-107F; ROHS: Yes
J901 = CONN_HDR_2X1: CON 1X2 PLUG SHRD TH 2.5MM SP 290H SN 134L; AGILE_PN: 210-82579; CAD_APPROVED: Yes; HEIGHT: 7.36MM; MFG_NAME01: CWB GROUP CO., LTD; MFG_PN01: TJC25020-2A; Package Type: Through Hole; ROHS: Yes; Temp Range: -25C to +85C
L901 = INDUCTOR: IND -- 1.5UH@100KHZ 9A 20% SMT; AGILE_PN: 180-75776; CAD_APPROVED: Yes; HEIGHT: 3MM; MFG_NAME01: VISHAY INTERTECHNOLOGY; MFG_PN01: IHLP2525CZER1R5M01; PART_TYPE: POWER; ROHS: Yes; Tolerance: 20%
R901 = RES: RES MF 3.3 OHM  1/8W 1% AEC-Q200 0603; AGILE_PN: 470-77775; CAD_APPROVED: Yes; FPLIST: RC0603_OV,RC0603,0603_CC; HEIGHT: 0.55MM; MFG_NAME01: KOA SPEER; MFG_PN01: RK73H1JTTD3R30F; ROHS: Yes; Temp Range: -55°C to +155°C; Temp_Range: -55°C to +155°C; Tolerance: 1%
R904 = RES: RES MF 10K 1/10W 1% AEC-Q200 0603; AGILE_PN: 470-80526; CAD_APPROVED: Yes; FPLIST: RC0603_OV,RC0603,0603_CC; HEIGHT: 0.55 MM; MFG_NAME01: VISHAY INTERTECHNOLOGY; MFG_PN01: CRCW060310K0FKEA; ROHS: Yes; Tolerance: 1%
R905 = RES: RES MF ZERO OHM 1/4W -- 1206; AGILE_PN: 470-80565; ASSY_OPT: DNP; CAD_APPROVED: Yes; FPLIST: RC1206_OV,RC1206,1206_CC; HEIGHT: 0.75 MM; MFG_NAME01: BOURNS; MFG_PN01: CR1206J/000ELF; ROHS: Yes
R906 = RES: RES MF 43.0K 1/16W 1% 0402; AGILE_PN: 470-77562; CAD_APPROVED: Yes; FPLIST: RC0402_25,RC0402_HD,0402_CC; HEIGHT: 0.4MM; MFG_NAME01: VISHAY INTERTECHNOLOGY; MFG_PN01: CRCW040243K0FKED; ROHS: Yes; Tolerance: 1%; VOLTAGE: 50V
R908 R913 R1758 R1759 R1761 R1763 = RES: RES MF 100K 1/16W 5% 0402; AGILE_PN: 470-75597; CAD_APPROVED: Yes; FPLIST: RC0402_25,RC0402_HD,0402_CC; HEIGHT: 0.40 MM; MFG_NAME01: VENKEL COMPANY; MFG_PN01: CR0402-16W-104JT; ROHS: Yes; Temp Range: -55C to +155C; Temp_Range: -55C to +155C; Tolerance: 5%; VOLTAGE: 50V
R910 = RES: RES MF 5.6K  1/16W 1% 0402; AGILE_PN: 470-30919; CAD_APPROVED: Yes; FPLIST: RC0402_25,RC0402_HD,0402_CC; HEIGHT: 0.40 MM; MFG_NAME01: YAGEO AMERICA; MFG_PN01: RC0402FR-075K6L; ROHS: Yes; Temp Range: -55°C ~ 155°C; Temp_Range: -55°C ~ 155°C; Tolerance: 1%; VOLTAGE: 50V
R305 R911 = RES: RES MF 100K 1/16W 5% 0402; AGILE_PN: 470-75597; ASSY_OPT: DNP; CAD_APPROVED: Yes; FPLIST: RC0402_25,RC0402_HD,0402_CC; HEIGHT: 0.40 MM; MFG_NAME01: VENKEL COMPANY; MFG_PN01: CR0402-16W-104JT; ROHS: Yes; Temp Range: -55C to +155C; Temp_Range: -55C to +155C; Tolerance: 5%; VOLTAGE: 50V
R912 = RES: RES MF 100 OHM 1/2W 1% AEC-Q200 0805; AGILE_PN: 470-80989; CAD_APPROVED: Yes; FPLIST: RC0805_OV,RC0805,0805_CC; HEIGHT: 0.7 MM; MFG_NAME01: PANASONIC; MFG_PN01: ERJ-P06F1000V; ROHS: Yes; Tolerance: 1%
R914 = RES: RES MF 1.0K 1/16W 5% 0402; AGILE_PN: 470-75555; CAD_APPROVED: Yes; FPLIST: RC0402_25,RC0402_HD,RC0402_X2,0402_CC,CAPC0402_L; HEIGHT: 0.41mm; MFG_NAME01: VISHAY INTERTECHNOLOGY; MFG_PN01: CRCW04021K00JNED; ROHS: Yes; Tolerance: 5%
R915 = RES: RES MF 1.0K 1/16W 5% 0402; AGILE_PN: 470-75555; ASSY_OPT: DNP; CAD_APPROVED: Yes; FPLIST: RC0402_25,RC0402_HD,RC0402_X2,0402_CC,CAPC0402_L; HEIGHT: 0.41mm; MFG_NAME01: VISHAY INTERTECHNOLOGY; MFG_PN01: CRCW04021K00JNED; ROHS: Yes; Tolerance: 5%
TP302 TP304 TP903 TP904 = TESTLOOP: TEST POINT PAD 50MIL DIA SMT, NO PART TO ORDER; AGILE_PN: 211-76644; ASSY_OPT: DNP; CAD_APPROVED: Yes; HEIGHT: 0.1MM; MFG_NAME01: NOTACOMPONENT; MFG_PN01: NOTACOMPONENT; ROHS: Yes
TVS901 = DIODE_TVS_BIDIR: DIODE SUPPRESSOR 16A@30NS 5V@1UA SOD-523; AGILE_PN: 480-76937; CAD_APPROVED: Yes; HEIGHT: 0.7MM; MFG_NAME01: on semiconductor; ROHS: Yes
U901 = MP8759GD_QFN12P: IC VREG SYNC STEP DOWN DCDC ADJ 8A 4.5-26V QFN12; 3D_Mechanical_Footprint_File: ftp://fcl.am.freescale.net/ALLEGRO/step/qfn12_0p5_3p1x2p1.step; AGILE_PN: 315-81301; CAD_APPROVED: Yes; HEIGHT: 1.05 MM; MFG_NAME01: MONOLITHIC POWER SYSTEMS; ROHS: Yes; Temp Range: -40°C to 125°C; Temp_Range: -40°C to 125°C; VOLTAGE: 4.5-26V
U902 = DML3006LFDS-7_A: IC LOAD SW 0.5-13.5V 10.5A 3-5.5V DFN2020-8; 3D_Mechanical_Footprint_File: ftp://fcl.am.freescale.net/ALLEGRO/step/dfn2020_0p5_sq2.STEP; AGILE_PN: 315-83392; CAD_APPROVED: Yes; HEIGHT: 0.9MM; MFG_NAME01: DIODES INC; Package Size: 8-VFDFN Exposed Pad; ROHS: Yes; Supply Voltage: 3-5.5V; Temp Range: -40°C to +85°C; VOLTAGE: 3-5.5V
C301 = CAP_NP: CAP CER 4.7UF 50V 10% X7R 1210; AGILE_PN: 150-76570; CAD_APPROVED: Yes; FPLIST: CC1210,1210_CC; HEIGHT: 2.7MM; MFG_NAME01: YAGEO AMERICA; MFG_PN01: CC1210KKX7R9BB475; ROHS: Yes; Tolerance: 10%; VOLTAGE: 50V
C302 C303 = CAP_POL: CAP ALEL 100uF 50V 20% -- SMD; AGILE_PN: 150-79137; CAD_APPROVED: Yes; HEIGHT: 10.5MM; MFG_NAME01: NICHICON; MFG_PN01: UUD1H101MNL1GS; ROHS: Yes; Tolerance: 20%; VOLTAGE: 50V
C304 = CAP_NP: CAP CER 0.22uF 50V 10% X5R 0402; AGILE_PN: 150-79999; CAD_APPROVED: Yes; FPLIST: CC0402_25,CC0402_HD,0402_CC; HEIGHT: 0.55MM; MFG_NAME01: TAIYO YUDEN; MFG_PN01: UMK105BJ224KV-F; Package Size: 0402; ROHS: Yes; Temp Range: -55°C to +85°C; Temp_Range: -55°C to +85°C; Tolerance: 10%; VOLTAGE: 50V
C306 = CAP_NP: CAP CER 2.2uF 10V 10% X5R 0402; AGILE_PN: 150-78974; CAD_APPROVED: Yes; FPLIST: CC0402_25,CC0402_HD,0402_CC,capc0402_l; HEIGHT: 0.55 MM; MFG_NAME01: TDK; MFG_PN01: C1005X5R1A225K; Package Size: 0402; ROHS: Yes; Tolerance: 10%; VOLTAGE: 10V
C307 = CAP_NP: CAP CER 4.7uF 16V 10% X5R 0603; AGILE_PN: 150-80061; CAD_APPROVED: Yes; FPLIST: CC0603_OV,CC0603,cc0603_0805_nsp,0603_CC_NSP; HEIGHT: 0.95MM; MFG_NAME01: MURATA; MFG_PN01: GRM188R61C475KE11D; ROHS: Yes; Temp Range: -55°C to + 85°C; VOLTAGE: 16V
D301 = DIODE: DIODE SCH 30V 200MA -- SOD323; AGILE_PN: 480-30039; CAD_APPROVED: Yes; HEIGHT: 1.15MM; MFG_NAME01: ON SEMICONDUCTOR; MFG_PN01: BAT54HT1G
F301 = FUSE: FUSE HIGH I2T 7A 32V 1206; AGILE_PN: 510-77913; CAD_APPROVED: Yes; HEIGHT: 0.8639MM; MFG_NAME01: LITTELFUSE; MFG_PN01: 0440007.WR; ROHS: Yes
J301 = USB6_TYPEC_SH4_1_A: CON 6 USB TYPE C PWR SHLD RA SMT 1MM SP  187H AU; 3D_Mechanical_Footprint_File: ftp://fcl.am.freescale.net/ALLEGRO/step/usb6p_typec_ra_sm.STEP; AGILE_PN: 211-81576; MFG_NAME01: FODOT ELECTRONICS CO.,LTD.; MFG_PN01: WT07FS-06GAA-A70BC32; Package Type: SMD/SMT
Q301 Q302 = NX3008NBKW_SOT323: TRAN NMOS SW 30V 350mA AEC-Q101 SC-70; AGILE_PN: 480-79736; CAD_APPROVED: Yes; HEIGHT: 1.1MM; MFG_NAME01: NEXPERIA; ROHS: Yes
R302 R1757 = RES: RES MF ZERO OHM JUMPER 1/2W AEC-Q200 0805; AGILE_PN: 470-81272; CAD_APPROVED: Yes; FPLIST: RC0805_OV,RC0805,0805_CC; HEIGHT: 0.6MM; MFG_NAME01: VISHAY INTERTECHNOLOGY; MFG_PN01: CRCW08050000Z0EAHP; ROHS: Yes; Temp Range: -55 °C to +155 °C; VOLTAGE: 150V
R304 = RES: RES MF 1M 1/16W 1% 0402; AGILE_PN: 470-80575; ASSY_OPT: DNP; CAD_APPROVED: Yes; FPLIST: RC0402_25,RC0402_HD,0402_CC; HEIGHT: 0.4MM; MFG_NAME01: BOURNS; MFG_PN01: CR0402-FX-1004GLF; ROHS: Yes; Tolerance: 1%
R350-R355 = RES: RES MF ZERO OHM 1/16W 5% 0402; AGILE_PN: 470-75394; ASSY_OPT: DNP; CAD_APPROVED: Yes; FPLIST: RC0402_25,RC0402_HD,RC0402_X2,0402_CC; HEIGHT: 0.45 MM; MFG_NAME01: ROHM; MFG_PN01: MCR01MZPJ000; ROHS: Yes; Tolerance: 5%; VOLTAGE: 1/16W
R356-R359 R1764 = RES: RES MF ZERO OHM 1/16W 5% 0402; AGILE_PN: 470-75394; CAD_APPROVED: Yes; FPLIST: RC0402_25,RC0402_HD,RC0402_X2,0402_CC; HEIGHT: 0.45 MM; MFG_NAME01: ROHM; MFG_PN01: MCR01MZPJ000; ROHS: Yes; Tolerance: 5%; VOLTAGE: 1/16W
SW301 = SW_DPDT_3: SW DPDT SLD 0.03A 50V TH; AGILE_PN: 510-78053; CAD_APPROVED: Yes; HEIGHT: 5.8MM; MFG_NAME01: FODOT ELECTRONICS CO.,LTD.; ROHS: Yes
TP301 TP303 TP305-TP310 = TESTLOOP: TEST POINT PAD 0.5MM DIA SMT, NO PART TO ORDER; AGILE_PN: 211-77484; ASSY_OPT: DNP; CAD_APPROVED: Yes; HEIGHT: 0.1MM; ROHS: Yes
U301 = PTN5110_QFN16: IC USB PD PHY 1PORT 2.7-5.5V HX2QFN16; AGILE_PN: 315-81118; CAD_APPROVED: Yes; HEIGHT: 0.4MM; MFG_NAME01: NXP SEMICONDUCTORS; MFG_PN01: PTN5110NHQZ; ROHS: Yes; Temp Range: ¨C40C to +85C; Temp_Range: ¨C40C to +85C; VOLTAGE: 2.7-5.5V
U302 = NX20P5090UK_15P_A: IC USB PWR SW 5A 2.5-20V WLCSP15; AGILE_PN: 315-81116; MFG_NAME01: NXP SEMICONDUCTORS; MFG_PN01: NX20P5090UKAZ
U303 = NX20P0407_WLCSP12_A: IC USB TYPE C PROTECTION +15KV/+8KV ESD WLCSP12; AGILE_PN: TMP-WF-31350; CAD_APPROVED: Yes; HEIGHT: 0.565 MM; MFG_NAME01: NXP SEMICONDUCTORS; PRE_APN: 312-81846; ROHS: Yes; Temp Range: -40C to +85C; VOLTAGE: +15KV/+8KV

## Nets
5V_PG: TP903.1(Pin1) U901.3(PG)
GND: C101.2 C102.2 C104.2 C105.2 C106.2 C107.2 C108.2 C109.2 C110.2 C111.2 C115.2 C116.2 C118.2 C119.2 C129.2 C130.2 C131.2 C132.2 C133.2 C136.2 C137.2 C138.2 C139.2 C140.2 C142.2 C143.2 C144.2 C145.2 C146.2 C151.2 C152.2 C153.2 C155.2 C301.2 C302.2 C303.2 C304.2 C305.2 C306.1 C307.2 C309.1 C801.2 C802.2 C803.2 C804.2 C805.2 C806.2 C807.2 C808.2 C809.2 C902.2 C903.2 C904.2 C905.2 C906.2 C907.2 C908.2 C910.2 C911.2 C928.2 C931.2 C932.2 C933.2 D901.A(ANODE) D902.C(CATHODE) J301.A12(GND1) J301.B12(GND2) J301.SH1 J301.SH2 J301.SH3 J301.SH4 J901.2 Q301.2(SOURCE) Q302.2(SOURCE) R313.2 R353.1 R354.1 R827.2 R838.2 R839.2 R840.2 R841.2 R910.2 R911.2 R1759.2 R1761.2 TVS901.1(A1) U101.A1(VSS1) U101.A17(VSS39) U101.C6(VSS10) U101.C8(VSS17) U101.C12(VSS26) U101.C14(VSS33) U101.D3(VSS3) U101.D15(VSS34) U101.E12(VSS27) U101.F3(VSS4) U101.F6(VSS11) U101.F8(VSS18) U101.F10(VSS23) U101.F15(VSS35) U101.G6(VSS12) U101.G12(VSS28) U101.H3(VSS5) U101.H9(VSS21) U101.H15(VSS36) U101.J6(VSS13) U101.J12(VSS29) U101.K3(VSS6) U101.K9(VSS22) U101.L7(VSS14) U101.M3(VSS7) U101.M6(VSS15) U101.M8(VSS19) U101.M10(VSS24) U101.M12(VSS31) U101.M15(VSS37) U101.N10(VSS30) U101.P3(VSS8) U101.P15(VSS38) U101.R4(VSS9) U101.R6(VSS16) U101.R8(VSS20) U101.R10(VSS40) U101.R12(VSS32) U101.R14(VSS41) U101.U1(VSS2) U101.U17(VSS25) U301.17(GND) U302.C3(GND1) U302.D3(GND2) U302.E3(GND3) U303.B3(GND) U303.D3(SBUEN) U801.25(VSS) U801.26(ADDR) U801.33(EXPAD) U802.3(GND) U803.6(GND) U804.6(GND) U805.6(GND) U901.2(PGND) U901.10(AGND) U902.4(GND) ; also on sheet 1 4 5 6 7 8 9 17 18 19 20 21 22 23
VBUS_IN: C302.1 C303.1 C905.1 C931.1 C932.1 C933.1 R302.2 R904.1 R905.1 R1757.2 U901.1(VIN) ; also on sheet 9
VBUS_OVLO_TH: R304.2 R1759.1 U302.B3(OVLO)
VCC_3V6: C907.1 R908.1 U901.9(VCC)
VDD_1V8: C115.1 C116.1 C802.1 L102.1 U101.L6(NVCC_WAKEUP_1) U101.L9(NVCC_WAKEUP_2) U101.L11(NVCC_WAKEUP_3) U802.5(VCC) ; also on sheet 5 6 7 8 9 17 18 21 22 23
VDD_3V3: C118.1 C119.1 C155.1 C307.1 C801.1 C804.1 C805.1 C806.1 C807.1 C808.1 C809.1 R213.1 R801.1 R802.1 R804.1 R808.1 R817.1 R913.2 R1762.1 R1765.1 U101.E8(VDD_USB_3P3) U101.H13(NVCC_AON) U101.K13(NVCC_GPIO) U301.3(VDD) U801.27(VDD_P) U801.31(VDD_I2C) U803.14(VDD) U804.14(VDD) U805.14(VDD) ; also on sheet 5 6 7 8 9 17 19 20 21 22 23
VDD_5V: C309.2 C910.1 C928.1 R912.1 R914.1 TP904.1(Pin1) U301.12(VCONN_IN) U902.7(VOUT) ; also on sheet 6 9 19 21
VDD_ANA_0V8: C130.1 C131.1 C132.1 C133.1 U101.C4(VDD_USB_0P8) U101.F13(VDD_ANA0_0P8) U101.M13(VDD_ANA1_0P8) ; also on sheet 17
VDD_ANA_1V8: C142.1 C143.1 C144.1 C145.1 C146.1 L102.2 R111.2 U101.E6(VDD_USB_1P8) U101.F12(VDD_ANA0_1P8) U101.L12(VDD_ANAVDET_1P8) U101.N8(VDD_ANA1_1P8)
VDD_SNVS_0V8: C102.1 U101.C10(VDD_BBSM_0P8_CAP)
VDD_SOC_0V85: C104.1 C105.1 C106.1 C107.1 C108.1 C109.1 C110.1 C111.1 U101.G7(VDD_SOC1) U101.G9(VDD_SOC4) U101.G11(VDD_SOC5) U101.H7(VDD_SOC2) U101.H11(VDD_SOC6) U101.K7(VDD_SOC3) U101.K11(VDD_SOC7) ; also on sheet 17
AUD_nINT: R845.2 ; also on sheet 6
AUD_PWREN: R831.2 ; also on sheet 6
BUF_POR: R808.2 R811.1 U802.4(Y)
CAN_STBY: R837.2 ; also on sheet 19
DCIN_15V: J901.1 R905.2
ENET1_nINT: U804.16(S1A) ; also on sheet 8
ENET1_nRST: R826.2 ; also on sheet 8
EXP3V3_EN: R858.2 ; also on sheet 21
EXP5V_EN: R806.2 ; also on sheet 21
EXP_GPIO_IO08: U805.1(S1B) ; also on sheet 21
EXP_GPIO_IO09: U805.4(S2B) ; also on sheet 21
EXP_GPIO_IO10: U805.8(S3B) ; also on sheet 21
EXP_GPIO_IO11: U805.11(S4B) ; also on sheet 21
EXP_GPIO_IO12: U803.1(S1B) ; also on sheet 21
EXP_GPIO_IO16: U804.1(S1B) ; also on sheet 21
EXP_GPIO_IO17: U804.4(S2B) ; also on sheet 21
EXP_GPIO_IO18: U803.4(S2B) ; also on sheet 21
EXP_GPIO_IO19: U803.8(S3B) ; also on sheet 21
EXP_GPIO_IO20: U803.11(S4B) ; also on sheet 21
EXP_GPIO_IO21: U804.8(S3B) ; also on sheet 21
EXP_nIRQ: R813.1 ; also on sheet 1
EXP_SEL: R836.2 R838.1 U803.15(SEL) U804.15(SEL) U805.15(SEL)
EXT1_PWREN: R825.2 ; also on sheet 7
GPIO_IO08: U805.2(D1) ; also on sheet 20
GPIO_IO09: U805.5(D2) ; also on sheet 20
GPIO_IO10: U805.7(D3) ; also on sheet 20
GPIO_IO11: U805.10(D4) ; also on sheet 20
GPIO_IO12: U803.2(D1) ; also on sheet 20
GPIO_IO16: U804.2(D1) ; also on sheet 20
GPIO_IO17: U804.5(D2) ; also on sheet 20
GPIO_IO18: U803.5(D2) ; also on sheet 20
GPIO_IO19: U803.7(D3) ; also on sheet 20
GPIO_IO20: U803.10(D4) ; also on sheet 20
GPIO_IO21: U804.7(D3) ; also on sheet 20
HP_DET: R812.2 ; also on sheet 6
I2C1_SCL: R828.1 R1008.1 ; also on sheet 6 7 17 20 21
I2C1_SDA: R830.1 R1009.1 ; also on sheet 6 7 17 20 21
I2C2_SCL: R820.1 ; also on sheet 17 20
I2C2_SDA: R824.1 ; also on sheet 17 20
I2C3_SCL: R1015.1 ; also on sheet 21
I2C3_SDA: R1016.1 ; also on sheet 21
I2C4_SCL: R1017.1 ; also on sheet 21
I2C4_SDA: R1018.1 ; also on sheet 21
I3C_TEMP_nINT: R860.2 ; also on sheet 7
IMU_INT1: U804.9(S3A) ; also on sheet 21
IOEXP_IO24: R851.2 ; also on sheet 21
IOEXP_IO25: R850.2 ; also on sheet 21
IOEXP_IO27: R852.2 ; also on sheet 21
LPD4/x_VDD2_1V1: C136.1 C137.1 C138.1 C139.1 C140.1 U101.K5(VDD2_DDR_2) U101.M5(VDD2_DDR_3) U101.N6(VDD2_DDR_4) U101.P4(VDD2_DDR_1) ; also on sheet 17 18
LPD4/x_VDDQ_0V6: C151.1 C152.1 C153.1 U101.F5(VDDQ_DDR_1) U101.H5(VDDQ_DDR_2) ; also on sheet 17 18
M2_nALERT: R818.2 ; also on sheet 7
M2_nDIS1: R835.2 ; also on sheet 7
M2_nDIS2: R832.2 ; also on sheet 7
M2_nRST: R833.2 ; also on sheet 7
M2_UART_nWAKE: R809.2 ; also on sheet 7
MIC/CAN_SEL: R829.2 ; also on sheet 23
NVCC_BBSM_1V8: C101.1 U101.E10(NVCC_BBSM_1P8) ; also on sheet 1 17 21
NVCC_SD2: C129.1 U101.N12(NVCC_SD2) ; also on sheet 17 20 22
PD_BYPASS: C306.2 U301.4(BYPASS)
PD_DBG_ACC: TP308.1(Pin1) U301.9(DBG_ACC)
PD_EN_SINK: R1760.1 U301.2(EN_SNK1)
PD_EN_SRC: TP306.1(Pin1) U301.16(EN_SRC)
PD_FRS_EN: TP307.1(Pin1) U301.1(FRS_EN)
PD_ILIM_5V_VBUS: TP309.1(Pin1) U301.6(ILIM_5V_VBUS)
PD_LD_nFLT: R1764.1 U301.11(FAULT_N)
PD_USB_CC1: U301.13(CC1) U303.A2(CC1)
PD_USB_CC2: U301.14(CC2) U303.B2(CC2) U303.C1(CON_SBU1) U303.C2(SBU1)
PD_USB_VBUS_IN: R302.1 R1757.1 TP302.1(Pin1) U302.A1(VINT1) U302.B1(VINT2) U302.C1(VINT3) U302.D1(VINT4)
PD_VBUS_PG: Q302.1(GATE) R1763.2 TP304.1(Pin1) U302.A2(ACK)
PMIC_nINT: R817.2 R822.2 ; also on sheet 17
PMIC_ON_REQ: R915.1 ; also on sheet 1 5 17
POR_B: U802.2(A) ; also on sheet 1 5 17
RTC_nINTA: R807.2 ; also on sheet 19
SAI3_MCLK: U804.3(S2A) ; also on sheet 6
SAI3_RXC: U803.3(S2A) ; also on sheet 6
SAI3_RXD: U803.12(S4A) ; also on sheet 6
SAI3_RXFS: U803.16(S1A) ; also on sheet 6
SAI3_TXD: U803.9(S3A) ; also on sheet 6
SD3_nRST: R821.2 R827.1 ; also on sheet 7
SD3_nWAKE: R810.2 ; also on sheet 7
SPI3_CLK: U805.12(S4A) ; also on sheet 7
SPI3_CS0: U805.16(S1A) ; also on sheet 7
SPI3_MISO: U805.3(S2A) ; also on sheet 7
SPI3_MOSI: U805.9(S3A) ; also on sheet 7
SYS_EN: D301.C(CATHODE) R352.2 R355.2
TCPC1_nINT: R823.1 ; also on sheet 9
TCPC_nINT: R805.2 R1765.2 TP310.1(Pin1) U301.10(ALERT_N)
USB_CC1_PD: J301.A5(CC1) R350.1 R358.1 TP301.1(Pin1)
USB_CC1_PD_OVP: R350.2 R356.2 U303.A1(CON_CC1)
USB_CC2_PD: J301.B5(CC2) R351.1 R359.1 TP303.1(Pin1)
USB_CC2_PD_OVP: R351.2 R357.2 U303.B1(CON_CC2)
USB_I2C_SCL: R1008.2 R1015.2 R1017.2 U301.8(I2C_SCL) ; also on sheet 9 19
USB_I2C_SDA: R1009.2 R1016.2 R1018.2 U301.7(I2C_SDA) ; also on sheet 9 19
USB_PD_VBUS: F301.1 J301.A9(VBUS1) J301.B9(VBUS2)
USB_PD_VBUS_F: C301.1 F301.2 R304.1 R305.1 U301.15(VBUS) U302.B2(VBUS1) U302.C2(VBUS2) U302.D2(VBUS3) U302.E1(VBUS4) U302.E2(VBUS5) ; also on sheet 9
VLDO3_1V8: R111.1 ; also on sheet 17
VLDO_3V3: C305.1 R1758.1 R1763.1 U303.A3(VSYS) ; also on sheet 9 19
VSYS_5V: C902.1 C903.1 C904.1 C908.1 C911.1 L901.2 R906.1 U901.5(VOUT) U902.1(VIN) U902.3(VCC) U902.8(VIN_2) ; also on sheet 7 9 17 19
N111686445: R901.1 U901.8(BST)
N111686449: C901.1 R901.2
N111686466: C901.2 L901.1 U901.7(SW)
N111686641: C906.1 D901.C(CATHODE) R904.2 R907.1 TVS901.2(A2)
N111686683: R907.2 U901.12(EN)
N111686689: R906.2 R910.1 U901.11(FB)
N111686749: R908.2 R911.1 U901.6(MODE)
N112247759: C803.1 R804.2 R811.2 U801.28(~{RESET})
N112248110: R813.2 R823.2 U801.32(~{INT})
N112248290: R801.2 R824.2 R830.2 U801.30(SDA)
N112248296: R802.2 R820.2 R828.2 U801.29(SCL)
N114579559: R805.1 U801.1(P0_0)
N114579565: R807.1 U801.2(P0_1)
N114579571: R806.1 U801.3(P0_2)
N114579577: R809.1 U801.4(P0_3)
N114579583: R812.1 U801.5(P0_4)
N114579589: R810.1 U801.6(P0_5)
N114579595: R850.1 U801.7(P0_6)
N114579601: R851.1 U801.8(P0_7)
N114598355: R852.1 U801.9(P1_0)
N114598565: R845.1 U801.10(P1_1)
N114629402: R818.1 U801.11(P1_2)
N114994571: R912.2 U902.5(BLEED)
N114994603: R213.2 R915.2 U902.2(EN)
N114997192: R913.1 U902.6(PG)
N114999418: D902.A(ANODE) R914.2
N115302368: R839.1 U803.13(EN)
N115508226: R841.1 U804.13(EN)
N115508248: R840.1 U805.13(EN)
N115511669: R829.1 U801.18(P2_1)
N115511689: R833.1 U801.19(P2_2)
N115511709: R832.1 U801.20(P2_3)
N115511729: R835.1 U801.21(P2_4)
N115511749: R858.1 U801.22(P2_5)
N115511769: R836.1 U801.23(P2_6)
N115511789: R837.1 U801.24(P2_7)
N115511922: R821.1 U801.13(P1_4)
N115511942: R825.1 U801.14(P1_5)
N115511962: R860.1 U801.15(P1_6)
N115511982: R826.1 U801.16(P1_7)
N115512059: R831.1 U801.17(P2_0)
N115512397: R822.1 U801.12(P1_3)
N115740207: Q301.3(DRAIN) R305.2 R1758.2 U302.A3(\\~{E}N)
N115740283: R353.2 R358.2 SW301.3(NO1)
N115740287: R352.1 R356.1 SW301.2(COMMON1)
N115740320: R354.2 R359.2 SW301.6(NO2)
N115740338: R355.1 R357.1 SW301.5(COMMON2)
N115740452: C304.1 D301.A(ANODE) Q301.1(GATE) R1760.2 R1761.1
N115740524: TP305.1(Pin1) U303.C3(FLAG)
N115740681: Q302.3(DRAIN) R1762.2 R1764.2
N115740897: R313.1 U301.5(SLV_ADDR)

Not connected (* = marked no-connect by the designer): SW301 1(NC1)* 4(NC2)*; U303 D1(CON_SBU2)* D2(SBU2)*; U802 1(NC)*; U804 10(D4)* 11(S4B)* 12(S4A)*; U901 4(NC)*

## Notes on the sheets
sheet 10
- USB TYPE-C PD
- USB C
  PD
- R1
- #'L' for PWR GOOD
- #Power Good Acknowledge (open-drain output)
- R2
- VOVLO threshold input
- CC OVP
- #C1 C2 PIN used for layout convenient
- SYS PWR SW
- # Control CC for Type-C PD power on/off control
- SW
- PD ADAPTER
- 1-2/4-5
- OFF <Default>
- 3-2/6-5
- ON
- I/OD
- O
- O
- SLV_ADDR
- Dev ADDR
- GND
- 1010000x
- #default "L"
- 10 K pull-up to BYPASS
- 1010001x
- O
- Unconnected
- 1010010x
- 100 K pull-up to BYPASS
- 1010011x
- O/OD
- default "UFP" mode
- # I2C ADDR: 0b'10100[10]X
sheet 11
- SYSTEM POWER
- When PERI 12V is required, VBUS_IN must be at least 12V!!!
- Main PWR
- # 5.2V/8A
- R1
- # EN: 1.35V-4.5V
- # EN: internal 600K PD
- R1
- Vfb=600mV
- Vout = (R1+R2) * Vfb / R2
- R2
- R2
- 5V PWR
- #bleeder
- LD SW
- VIN:  0.5-13.5V
  VCC: 3.0-5.5V
  Imax:10.5A
- PWR LED
- EN PD: 76-124K
  EN > 2.0V
sheet 12
- IO MUX / EXP
- I2C IO EXP
- #PU RES for IRQ
- #OD, PU MX93
- #BUF w/ OD
- #Share IRQ due to TCPC level trigger rather edge trigger
- #1 MHz I2C I/F for IRQ fast response!!!
- 1 MHz I2C (Fm+)
- #I2C ADDR: 0b'01000[10]x
- SHARED GPIO MUX
- ENET
- CODEC
- CODEC
- M.2 802.15.4
- IMU
- #GPIO_IO12
- #GPIO_IO08
- #GPIO_IO16
- #GPIO_IO17
- #GPIO_IO18
- #GPIO_IO19
- #GPIO_IO09
- #GPIO_IO10
- #GPIO_IO21
- #GPIO_IO20
- #GPIO_IO11
- #GPIO_IO12
- #GPIO_IO08
- #GPIO_IO16
- #GPIO_IO18
- #GPIO_IO19
- #GPIO_IO09
- #GPIO_IO10
- #GPIO_IO17
- #GPIO_IO21
- #GPIO_IO20
- #GPIO_IO11
- EXPI
- EXPI
- EXPI
- SEL=L:   SxA->Dx
- SEL=L:   SxA->Dx
- SEL=L:   SxA->Dx
- SEL=H:  SxB->Dx
- SEL=H:  SxB->Dx
- SEL=H:  SxB->Dx
sheet 13
- MCIMX93-9x9 package Quick Start Board
- MCIMX93-QSB
- Table of Content
- Revision History
- Page 1
- Cover
- Rev. Code
- Date
- By
- Description
- Page 2
- Block Diagram
- A
- 2022-05-06
- nxa13729
- Initial version
- Page 3
- PWR TREE
- A1
- 2022-09-01
- nxa13729
- DNP R1767, chang to 1.8V PU due to USB ID power domain is 1.8V
- Page 4
- CPU PWR
- Add R823 as USB TCPC shared interrupt to support level trigger mode
- Change R812 connected with HP_DET which used as audio jack detection
- Page 5
- LPDDR4/X
- Add R845 connected with AUD_nINT to maintain the SW compatible
- Add R1822, DNP R1203 as audio jack detection to GPIO IRQ path
- Page 6
- CPU IO/PHY
- Add R956,R957 for M.2 compatible design
- Add U1004,D1011,D1012,R1072,R1073-R1085,C1021-C1024,BT1001,TP1015-TP1021 RTC module circuits
- Page 7
- CPU MISC
- Change L503,L504 to 0 OHM  R530,R531
- Add R958,R959 to use RTC_CLKO
- Page 8
- eMMC/MicroSD
- Add R1823
- Add R745,R748, J1710,J1711，used for Audio Hat Board
- Page 9
- PMIC
- Remove TP1954, TP1955, TP1956,TP1958
- Add R850,R851,R852,R853,R854 for backup
- Page 10
- IO MUX
- DNP R1433,R1434,R1435
- Add TEMP Sensor U915，R860,R861,R862,R863,C955,C956
- Page 11
- SYS PWR
- PMIC PN Change from PCA9451 to PCA9451A, delete   VLDO3_1V8
- DNP C728
- Page 12
- USB PD
- ADD R870, R871 for validation
- Add U908 level shift LSF0102 to replace the level shifter inside PMIC
- Page 13
- USB1 C
- ADD TP218, TP219,TP220,TP221 for validation
- Page 14
- ENET1
- A2
- 2023-06-25
- nxa13729
- Update U101 symbol for USB ID power domain
- Page 15
- M.2
- Change VDD_SOC_0V8 to VDD_SOC_0V85，Remove R870, Add R111,Install C728
- Change ADC power rail with more CAP+FB, install C720, change L102 to 1K OHM FB
- Page 16
- EXPI/IMU/MFi/ADC
- Add R211 to support LPDDR4/X w/ 2CS
- Add R102 to support 100-ball LPDDR4/X
- Page 17
- CAN
- Default use PMIC internal Level shift for I2C1. Take U908 NTS0104GU12 as backup.
- Install R717,R719, R713,R712
- Remove TP1959, Add R858, for GPIO EXP3V3_EN
- Page 18
- CODEC
- Add C931,C932,C933 for better performance
- Remove R314, C308. Delect the net of USB_GND_CHASSIS
- Page 19
- BOOT CFG/PDM
- Remove the net name of HPL_ZOBEL
- Page 20
- REMOTE DEBUG
- Add C1230, C1231 for the power of WM8962.
- Install R1203 to keep WM8962B GPIO5 PU
- Change the symbol of GND Testloop: TP1901, TP1905,TP1906
- Update J1101, J1708  USB Type C connector to longer pin length (footprint compatible) to improve the reliability of soldering
- Page 21
- MECHANICS
- Change R745 to 33ohm for better audio performance
- Remove J1711 and R748, Add R855 and R856
- Page 22
- NOTE
- Page 23
- IOMUX
- A3
- 2023-11-10
- nxa13729
- Using GPIO(U801.P0_2) to control power EXP_5V to fix LCD fliker issue
- Change R1420 to 1K (DNP default) due to mid-voltage caused by  LSM6DSOXTR internal PD
- Remove TP1906
- Update U101 symbol for pinname change （E10）
- Change the value of resistors R855 and R856 to 0R
- Add R360, D302 ( DNP default)  for USB PWR detection backup
- Update U502, U503 due to ESD EOL
- A4
- 2024-06-27
- -
- change C102 from 0.22uF to 1.0uF
- change U201 DDR from MT53E1G16D1FW-046 AAT:A to MT53E1G16D1ZW-046 AAT:C due to EoF
- Preliminary - Subject to Change without Notice!
- change U404  from SGM8709YN5G to MCP6546T-E/OT due to leakage
- all changes do not impact layout, this schematic version is paired with layout LAY-54852_A3
- This board was designed for maximum flexibility in
  software  development and demonstrates multiple
  functions possible with i.MX processors. Although best
  design practices have been applied, some areas may
  not be suitable for a mass-production design.
- A5
- 2025-06-12
- -
- update part number of U101
- update some design note or typo
- all changes do not impact layout, this schematic version is paired
  with layout LAY-54852_A3
sheet 14
- BLOCK DIAGRAM
- SYS PWR
- PMIC
- M.2 NGFF
- USB C
     PD
- PWR
- SD3
  UART/SAI1
- M.2
- NXP PCA9451A
- KEY-E:WiFi/BT...
- # NXP Wi-Fi/BT 1x1 WiFi 6 (802.11ax)
- x16 bits
- DRAM
- DRAM
- LPDDR4/X: 2GB <x16b>
- USB 2.0
- USB 2.0 DRP
- USB C
- eMMC 5.1
- x8 SDHC
- USB1
- TYPE-C connector
- SD1
- N
- X
- P
- CONNECTIVITY
- 16GB HS400
- ENET
- Gigabit NET
- RGMII
- Realtek RTL8211
- RJ45
- i.MX93
- # AVB, 1588, and IEEE 802.3az
- ARM:
      x2 CORTEX-A55 (1.7GHz)
      x1 CORTEX-M33 (250MHz)
  ML:
      0.5 TOPs Ethos-U65 NPU (1GHz)
- IMU
- I3C/I2C
- RS232
- CORTEX-A55 / CORTEX-M33 DEBUG
- ST LSM6DSOXTR
- UART
- USB C
- SENSOR
- FTDI XCVR
- Remote Debug Support
- CAN
- ADC
- CAN
- ADC
- NXP TJA1051T/3
- x12 bit
- PDM
- WTB CN
- ADC: HDR CN + VSYS
- PDM
- PDM MIC ONBOARD
- HP OUT/MIC
- AUX I2C
- CODEC
- I2S
- PDM MIC
- PDM MIC
- PDM MIC
- HDR
- I2C
- SAI3
- I2C/GPIO
- SW
- Cirrus Logic
    WM8962B
- SPK OUT
- SD2
- JTAG/SWD
- I2C/SPI/UART...
- MicroSD
- JTAG/SWD
- EXP CN
- SD3.0
- DEBUG
- UART/I2C/SPI...
- # Audio HAT / RFID / PDM...
- MicroSD
- MicroSD
- HDR
- HDR
sheet 15
- i.MX93 EVK PWR TREE
- PMIC: PCA9451AHN
- SoC: i.MX93
- SEQ
- REGULATOR
- VOL (V)
- MAX I (mA)
- ITEM
- PWR RAIL
- TYP VOL(V)
- REQ I (mA)
- 1
- LDO1
- 1.8
- 10
- 1
- NVCC_BBSM_1V8
- 1.8
- 2
- USB C SNK PD
- -
- PMIC_ON_REQ
- VBUS_IN
- VSYS_5V
- USB C
     PD
- DCDC BUCK
- 2
- T1
- BUCK1/3 DP
- 0.85
- 4000
- 2
- VDD_SOC
- DVS
- Ref to DS
- (5V), 12-20V
- MPS MP8759GD
- 3
- T2
- LDO4
- 0.8
- 200
- 3
- VDD_ANA_0P8
- 0.8
- 186
- 4
- 4
- VSYS_5V
- 5
- T4
- BUCK5
- 1.8
- 2000
- 4
- VDD_ANA_1P8/NVCC_WAKEUP
- 1.8
- 389
- 6
- T5
- BUCK6
- 1.1
- 1500
- 5
- VDD2_DDR/LPD4 VDDQ
- 1.1
- 676
- 7
- T6
- BUCK2
- 0.6
- 2000
- 6
- VDDQ_DDR (0.6V for LPD4x)
- 0.6
- 360
- 8
- T7
- BUCK4
- 3.3
- 3000
- 7
- NVCC_GPIO/VDD_USB_3P3
- 3.3
- 8
- T7
- Load Switch
- -
- 400
- 7
- SD_CARD
- 3.3
- 9
- T8
- LDO5
- 1.8/3.3
- 150
- 8
- NVCC_SD2
- 1.8/3.3
- -
- -
- -
- 12
- POR_B
- --
- --
- POR_B
- LPDDR4/X
- VDD1 <1.8V>
  VDD2 <1.1V>
  VDDQ <0.6V/1.1V>
- VPCIe_3V3
- DCDC BUCK
- MPS MP2147
- 3.3V/4A
- eMMC
- VCCQ <1.8V>
  VCC <3.3V>
- VDD_5V
- Load SW
- MicroSD
- MOSFET
- 5V/3A
- VCC <3.3V>
- Audio CODEC
- AVDD/DVDD <3.3V>
  SPKVDD <5V>
- ETHERNET
- DVDD_REG <1.8V>
  AVDD/DVDD <3.3V>
- USB C DRP
- VBUS <5V>
- M.2 KEY-E
- 3.3V
- EXPI
- 3.3V
- 5V
- PDM/CAN
- 3.3V
- 5V
sheet 16
- i.MX93 PWR
- # NVCC_BBSM_1P8: 1.8V / 2mA
- Imax = N x C x V x (0.5 x F)
- # VDD_SOC
- # VDD_xxx_0P8: 0.8V
- # VDD_xxx_1P8: 1.8V
- #0.6V for LPDDR4X
- #1.1V for LPDDR4
- # VDD_USB_3P3: 3.3V
- NOTE:
- All the CAPs on this page except C142 and C143 need to be placed
  under the BGA as close to the associated balls as possible.
